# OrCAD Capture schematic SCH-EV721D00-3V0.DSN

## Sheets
1 Block Diagram
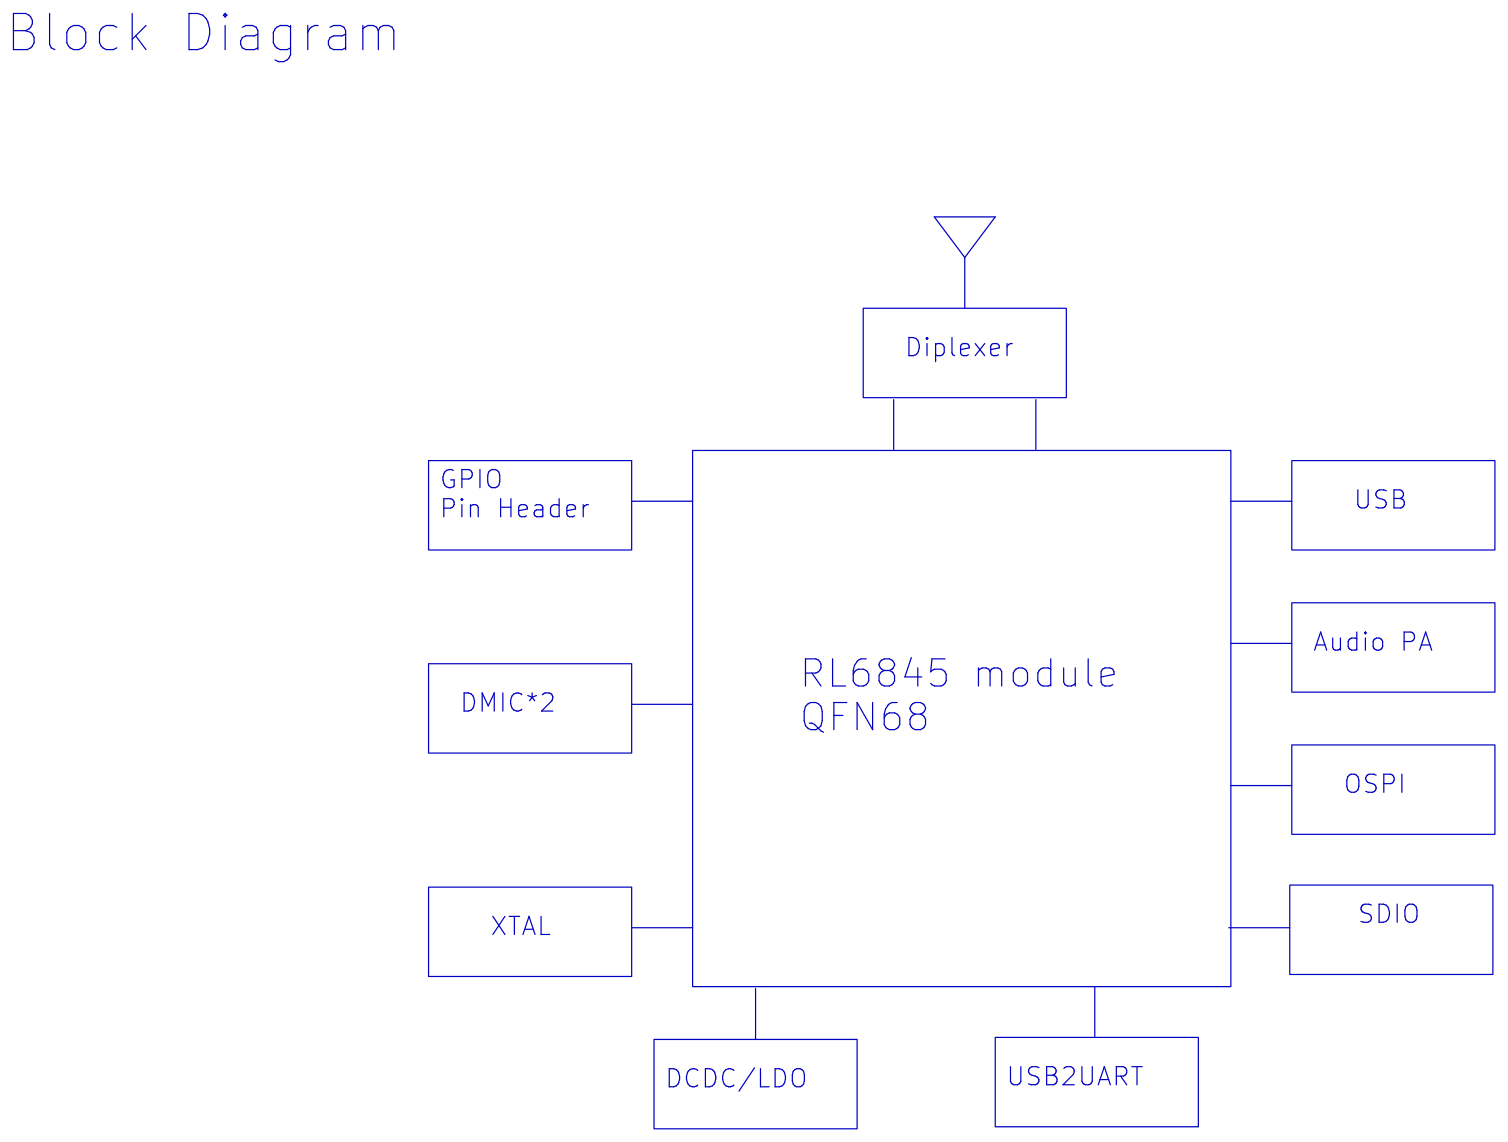
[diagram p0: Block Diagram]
2 Power Tree
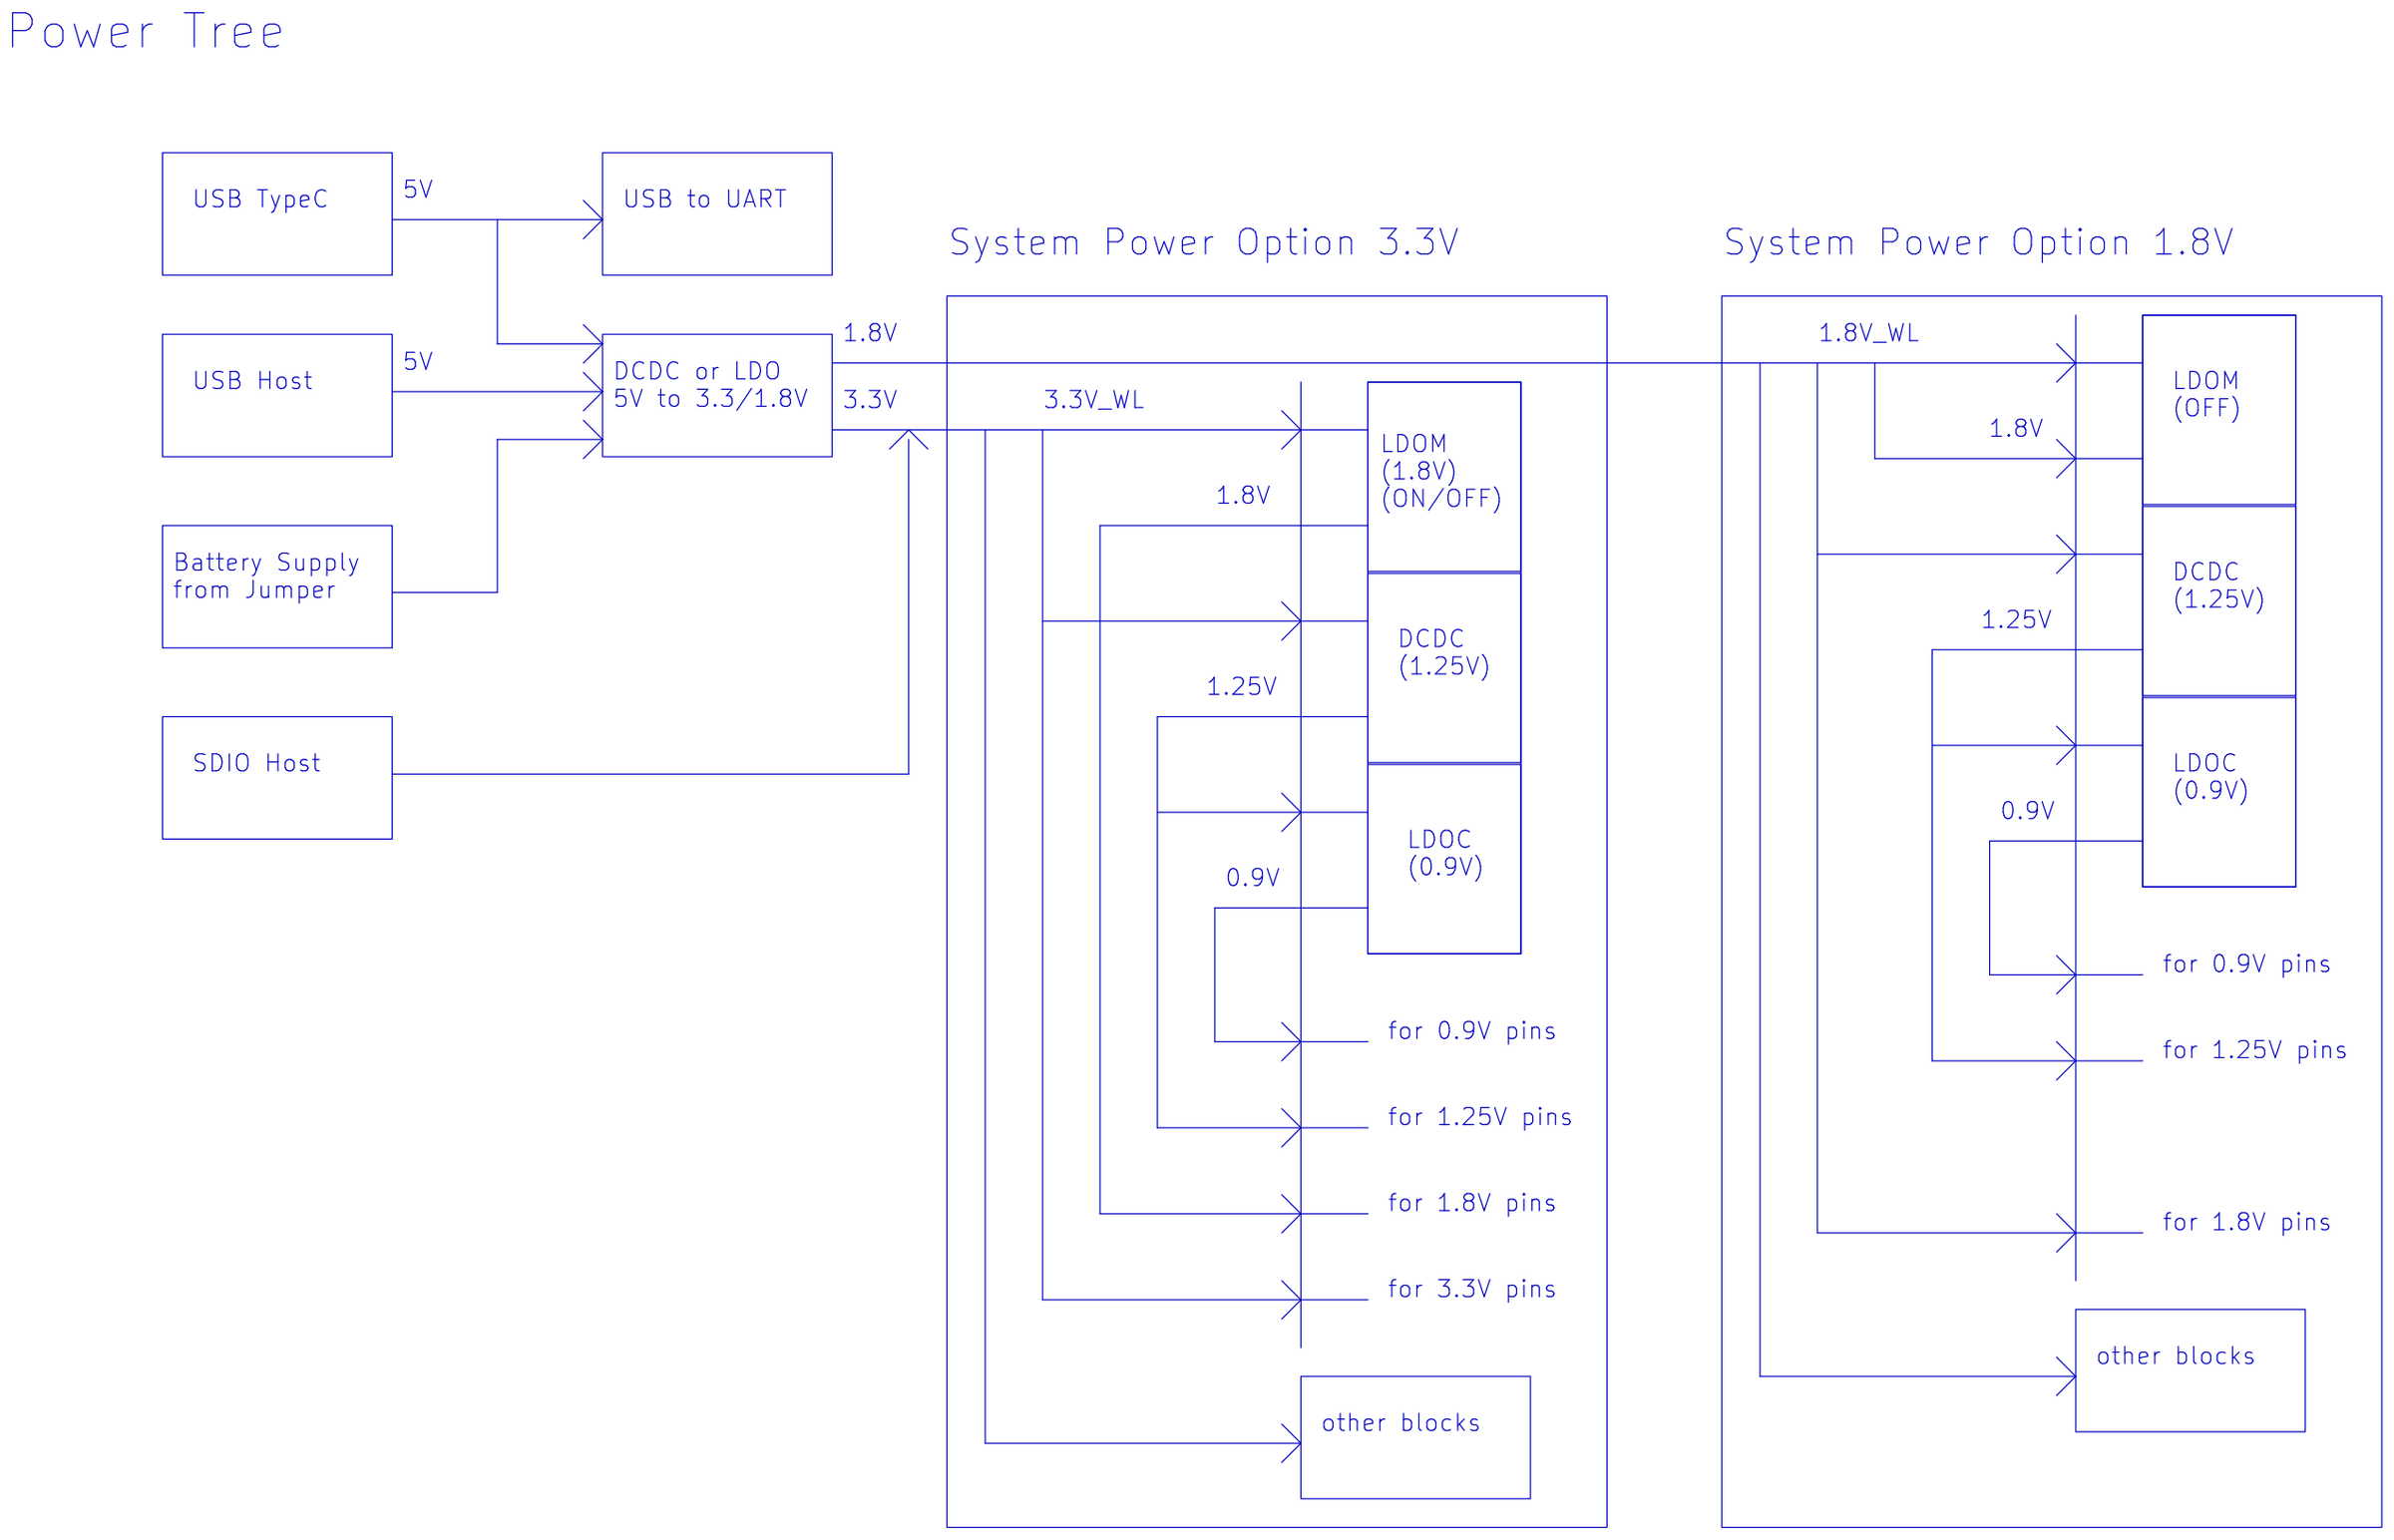
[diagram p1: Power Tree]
3 Power & USB: size A3; title: Power & USB
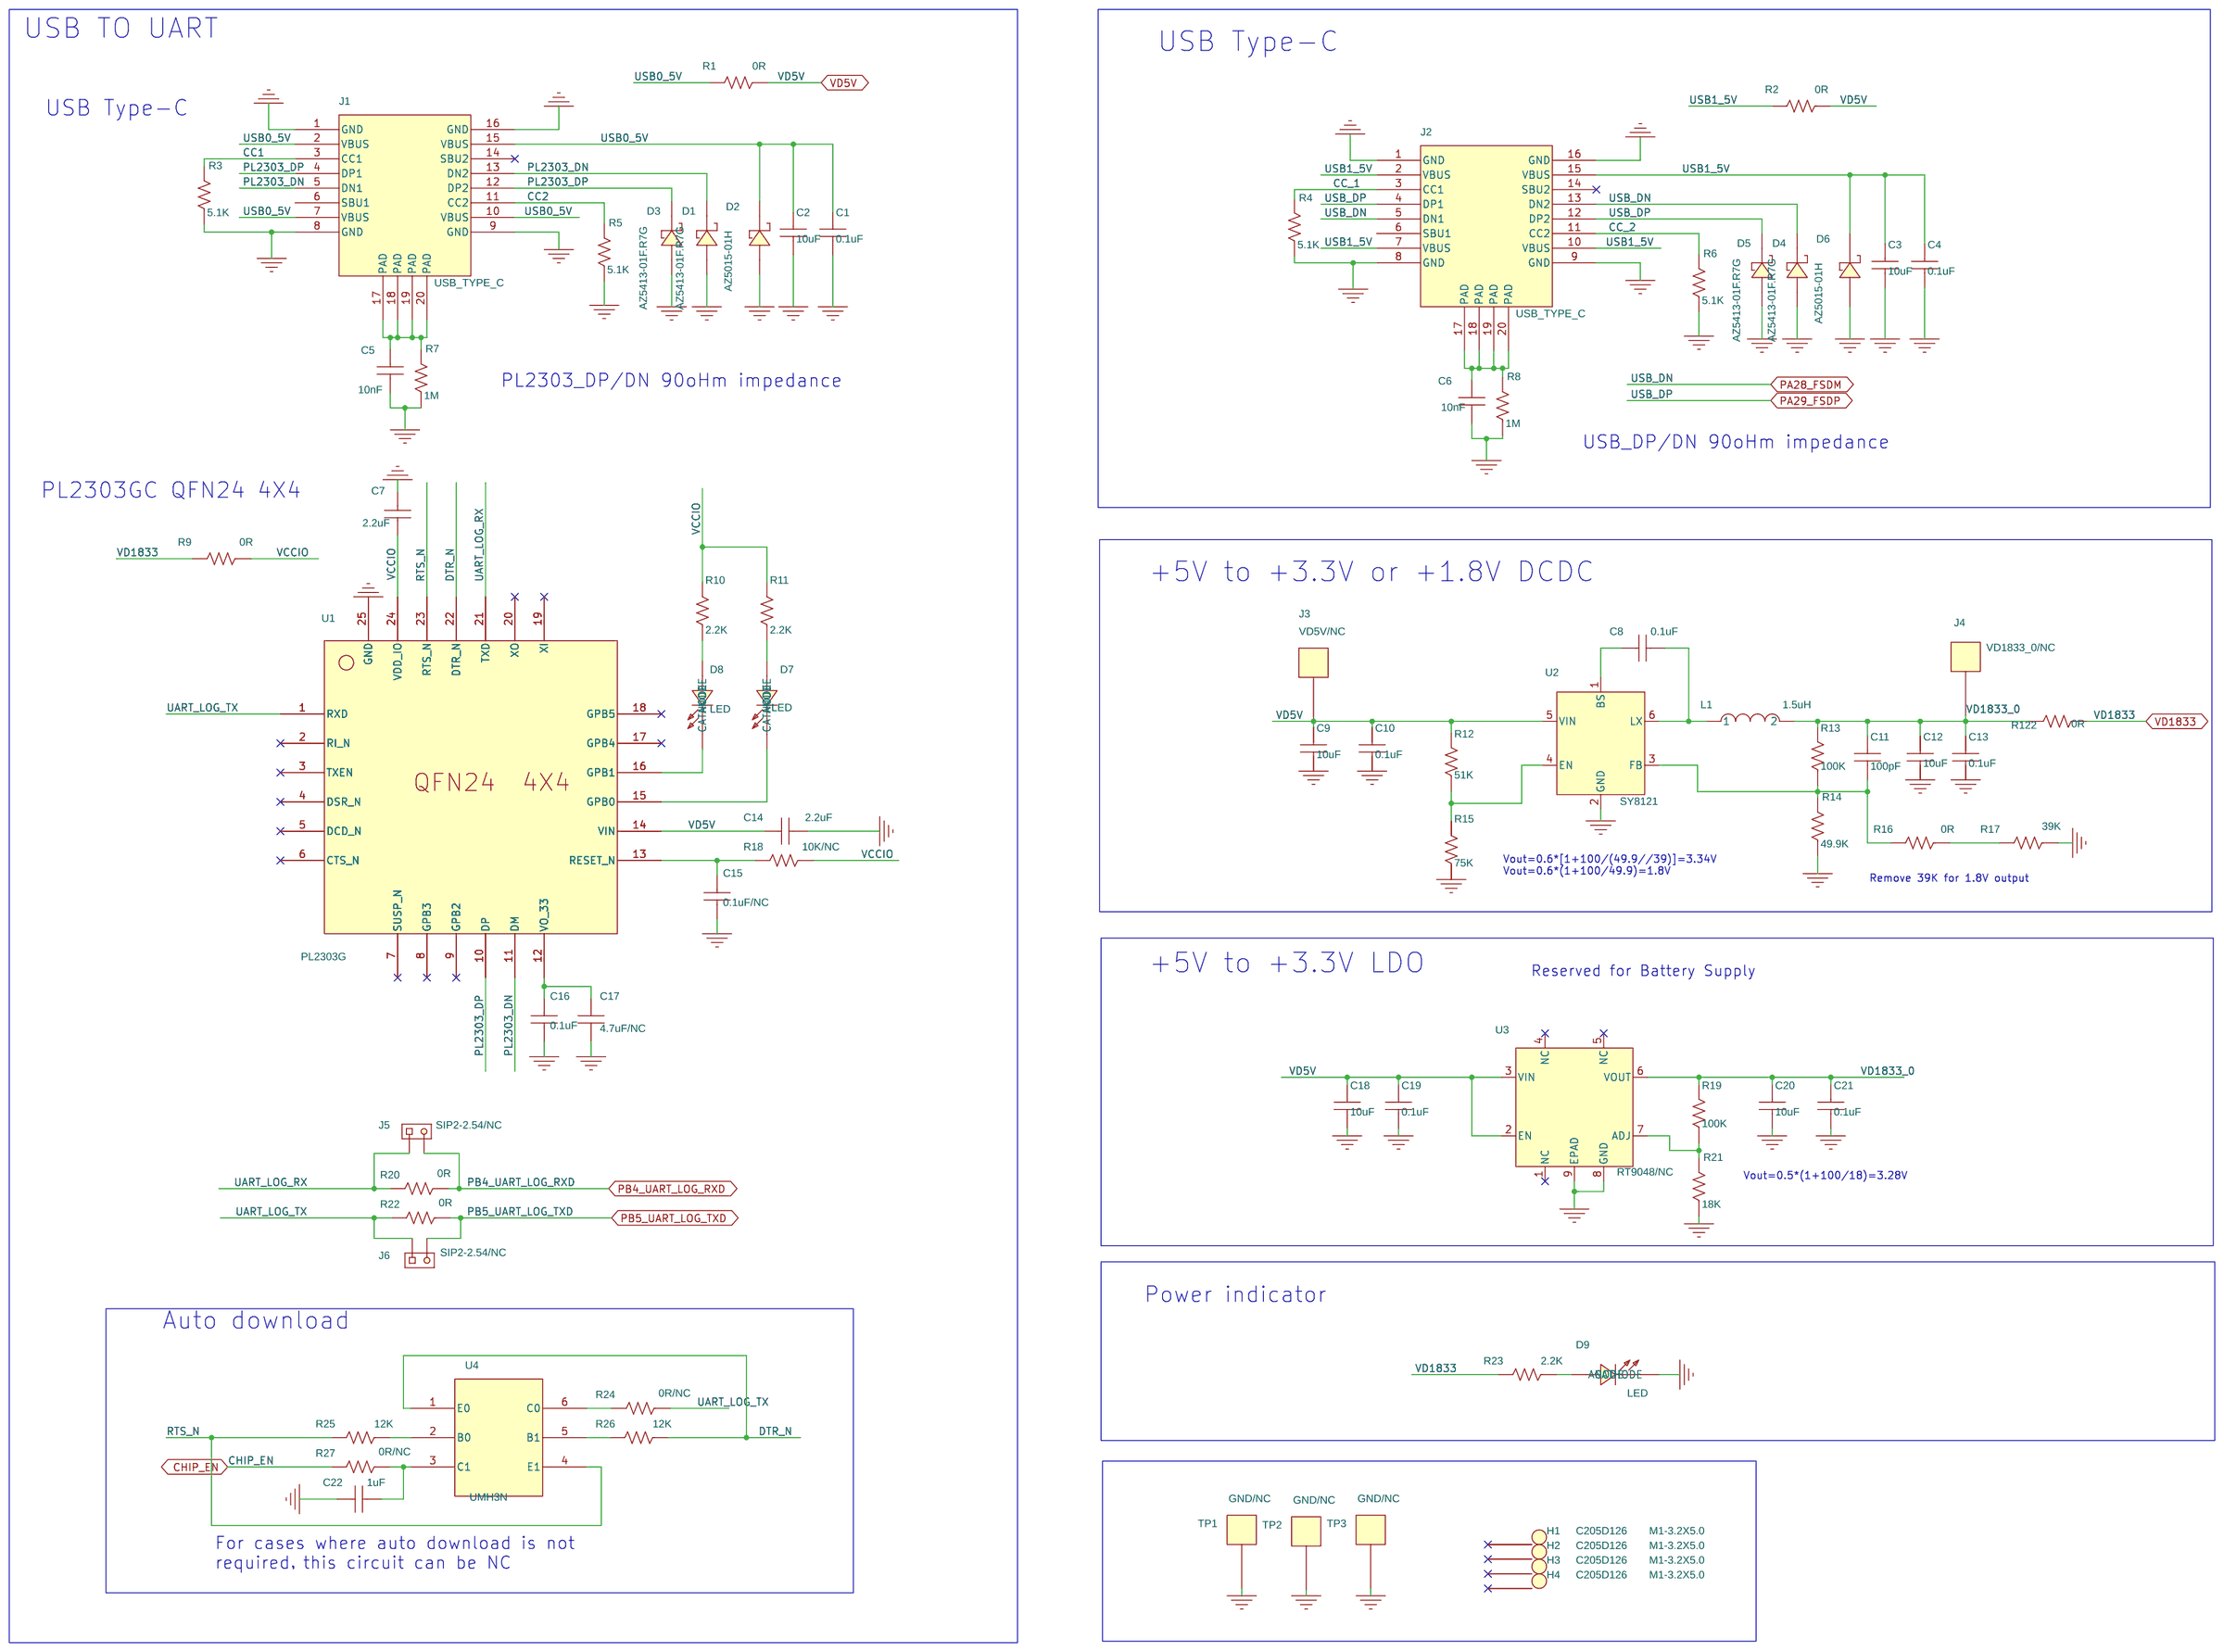
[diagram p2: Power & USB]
4 Module: size A3; title: Module
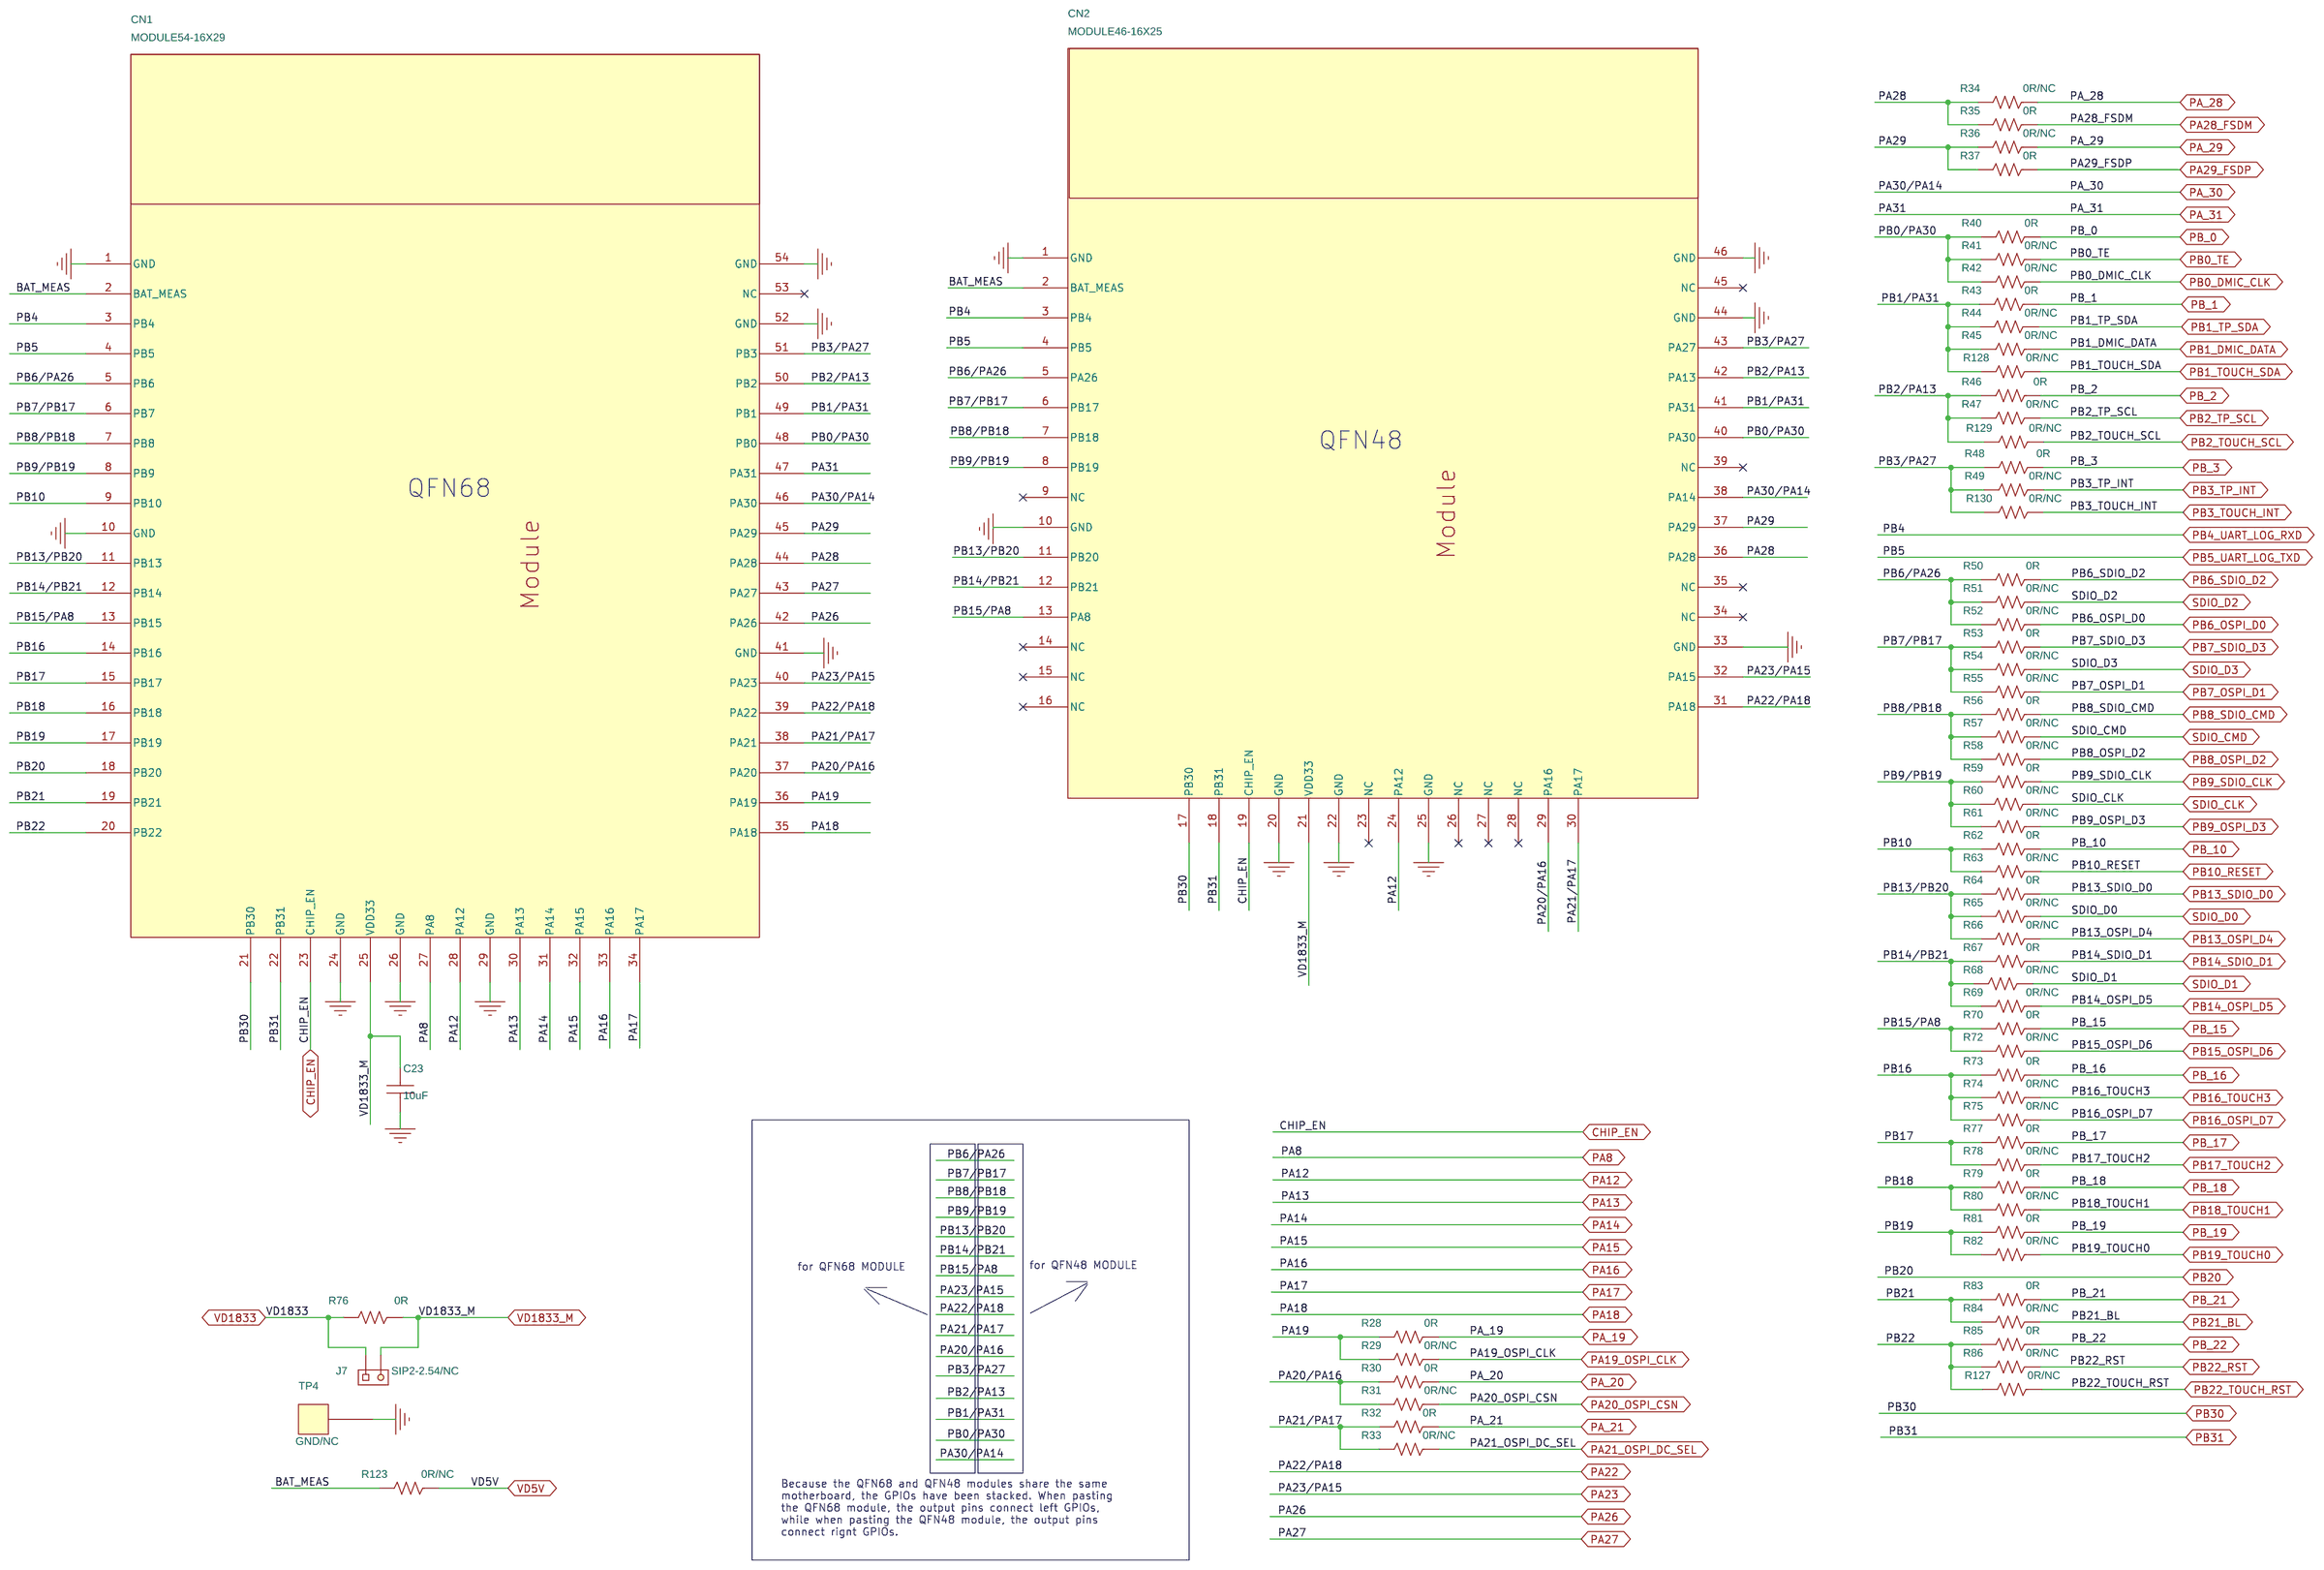
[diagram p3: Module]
5 Function: size B; title: Function
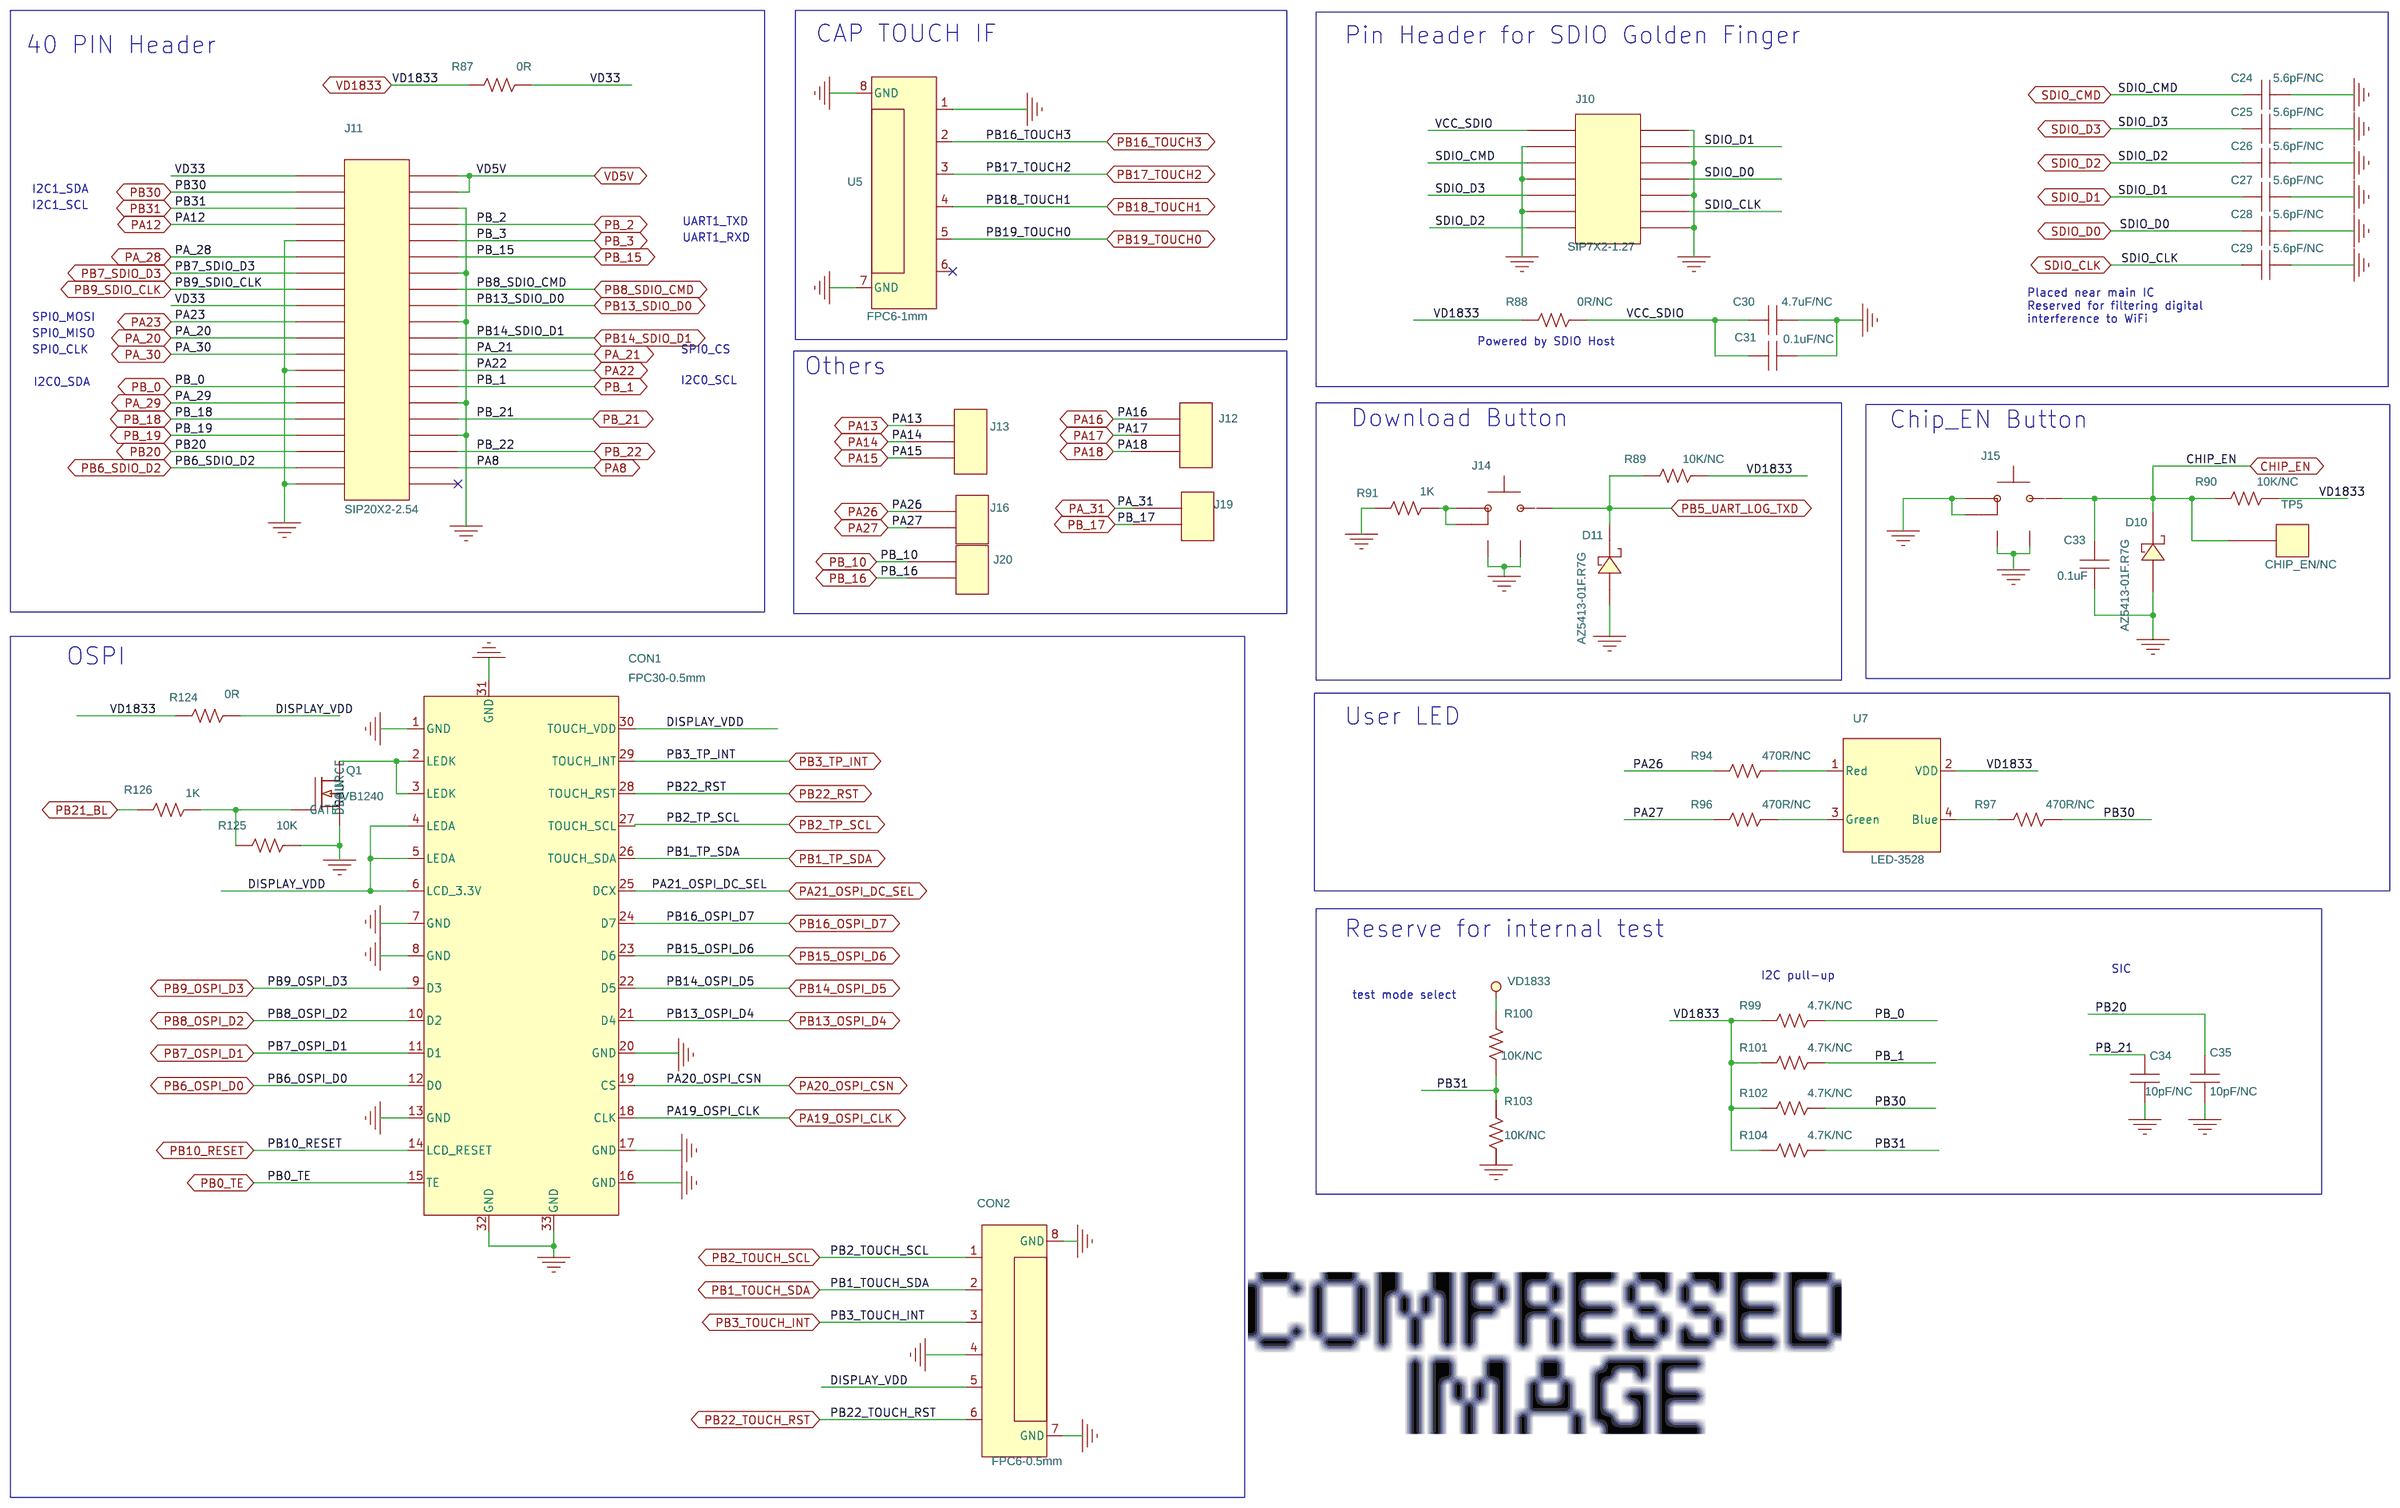
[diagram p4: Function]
6 Audio: size B; title: Audio
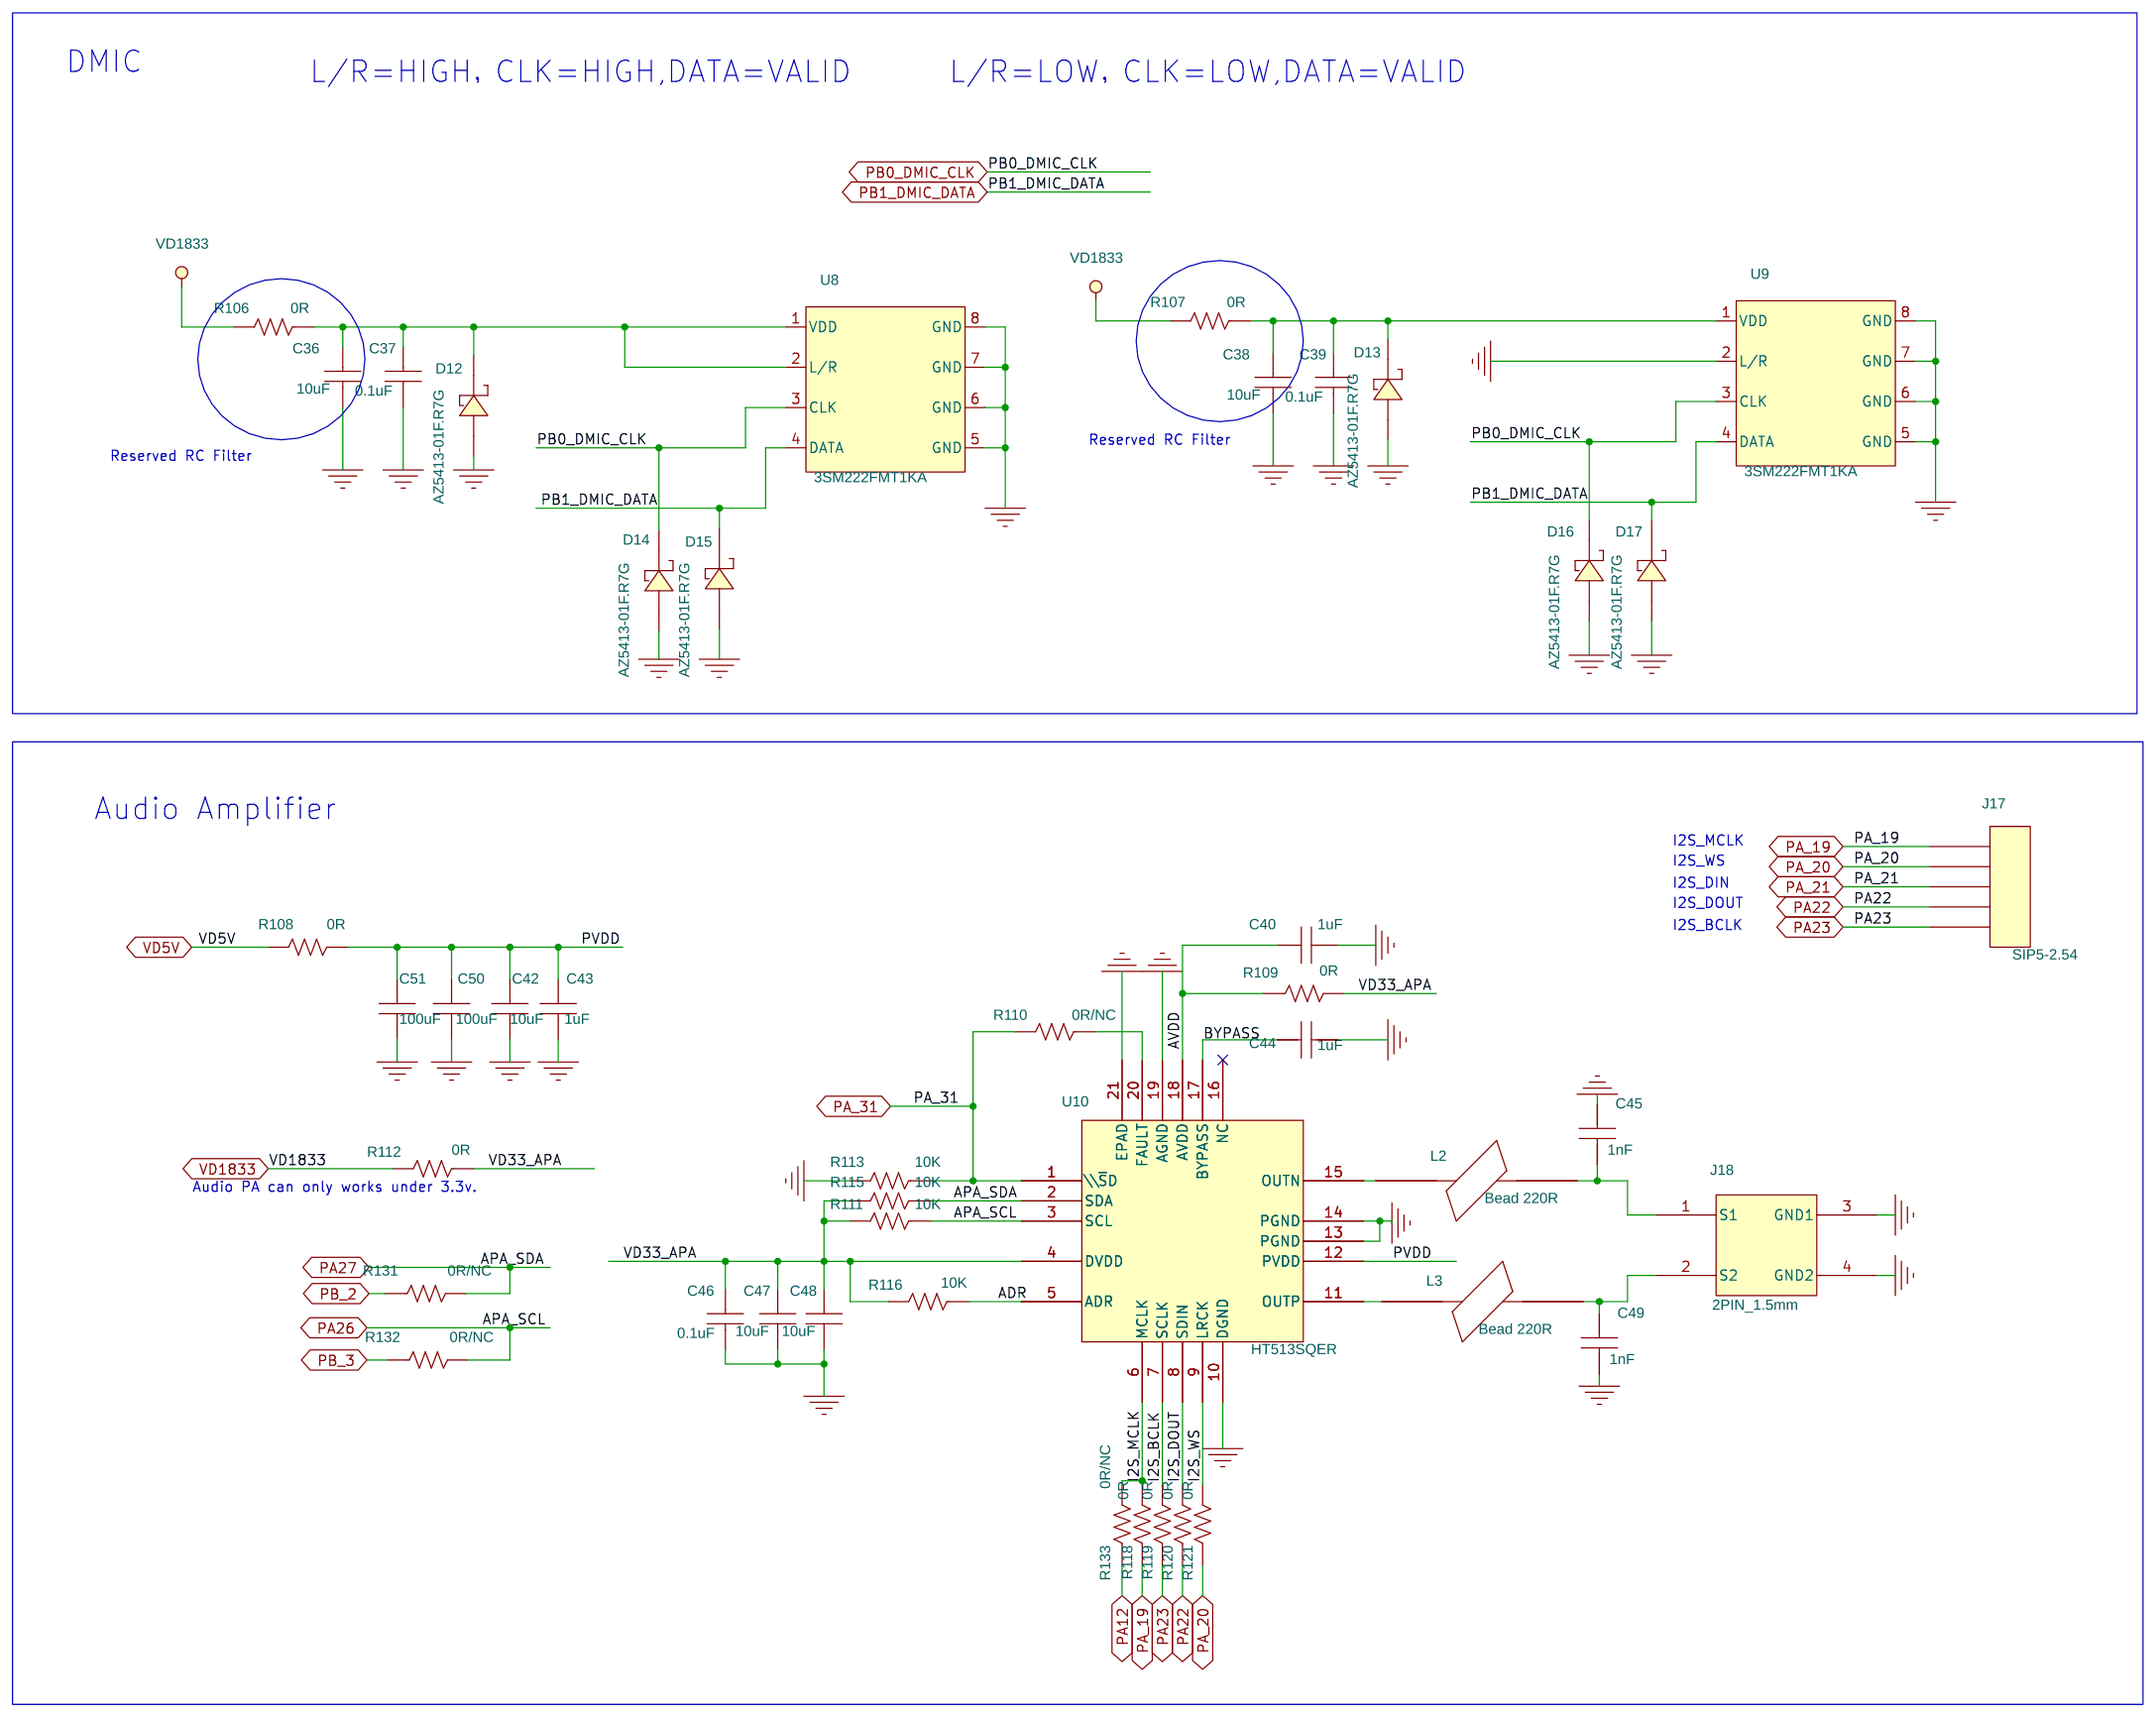
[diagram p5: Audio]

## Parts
sheet Audio
C36  10uF  [C0603]
C37  0.1uF  [C0402]
C38  10uF  [C0603]
C39  0.1uF  [C0402]
C40  1uF  [C0402]
C42  10uF  [C0603]
C43  1uF  [C0402]
C44  1uF  [C0402]
C45  1nF  [C0402]
C46  0.1uF  [C0402]
C47  10uF  [C0402]
C48  10uF  [C0402]
C49  1nF  [C0402]
C50  100uF  [C0805]
C51  100uF  [C0805]
D12  AZ5413-01F.R7G  [D0402-AZ5413]
D13  AZ5413-01F.R7G  [D0402-AZ5413]
D14  AZ5413-01F.R7G  [D0402-AZ5413]
D15  AZ5413-01F.R7G  [D0402-AZ5413]
D16  AZ5413-01F.R7G  [D0402-AZ5413]
D17  AZ5413-01F.R7G  [D0402-AZ5413]
J17  SIP5-2.54  [SIP5-2.54]
J18  2PIN_1.5mm  [Bar-Connector4]
L2  Bead 220R  [L0402]
L3  Bead 220R  [L0402]
R106  0R  [R0402]
R107  0R  [R0402]
R108  0R  [R0805]
R109  0R  [R0402]
R110  0R/NC  [R0402]
R111  10K  [R0402]
R112  0R  [R0402]
R113  10K  [R0402]
R115  10K  [R0402]
R116  10K  [R0402]
R118  0R  [R0402]
R119  0R  [R0402]
R120  0R  [R0402]
R121  0R  [R0402]
R131  0R/NC  [R0402]
R132  0R/NC  [R0402]
R133  0R/NC  [R0402]
U8  3SM222FMT1KA  [LGA8-4X3]
U9  3SM222FMT1KA  [LGA8-4X3]
U10  HT513SQER  [QFN16-0.5-4X4-EPAD2.65X2.65]
sheet Function
C24  5.6pF/NC  [C0402]
C25  5.6pF/NC  [C0402]
C26  5.6pF/NC  [C0402]
C27  5.6pF/NC  [C0402]
C28  5.6pF/NC  [C0402]
C29  5.6pF/NC  [C0402]
C30  4.7uF/NC  [C0603]
C31  0.1uF/NC  [C0402]
C33  0.1uF  [C0402]
C34  10pF/NC  [C0402]
C35  10pF/NC  [C0402]
CON1  FPC30-0.5mm  [FPC30-0.5-S]
CON2  FPC6-0.5mm  [FPC6-0.5]
D10  AZ5413-01F.R7G  [D0402-AZ5413]
D11  AZ5413-01F.R7G  [D0402-AZ5413]
J10  SIP7X2-1.27  [SIP7X2-1.27]
J11  SIP20X2-2.54  [SIP20X2-2.54]
J12  SIP3-2.54  [SIP3-2.54]
J13  SIP3-2.54  [SIP3-2.54]
J14  Reset Button  [SW-PB-5-KAN4548-1]
J15  Reset Button  [SW-PB-5-KAN4548-1]
J16  SIP2-2.54  [SIP2-2.54]
J19  SIP2-2.54  [SIP2-2.54]
J20  SIP2-2.54  [SIP2-2.54]
Q1  VB1240  [SOT-23]
R87  0R  [R0805]
R88  0R/NC  [R0805]
R89  10K/NC  [R0402]
R90  10K/NC  [R0402]
R91  1K  [R0402]
R94  470R/NC  [R0402]
R96  470R/NC  [R0402]
R97  470R/NC  [R0402]
R99  4.7K/NC  [R0402]
R100  10K/NC  [R0402]
R101  4.7K/NC  [R0402]
R102  4.7K/NC  [R0402]
R103  10K/NC  [R0402]
R104  4.7K/NC  [R0402]
R124  0R  [R0603]
R125  10K  [R0402]
R126  1K  [R0402]
TP5  CHIP_EN/NC  [SIP1-2.54]
U5  FPC6-1mm  [FPC6-1]
U7  LED-3528  [LED-3528]
sheet Module
C23  10uF  [C0603]
CN1  MODULE54-16X29  [MODULE54-16X29]
CN2  MODULE46-16X25  [MODULE46-16X25-EVB]
J7  SIP2-2.54/NC  [SIP2-2.54]
R28  0R  [R0402]
R29  0R/NC  [R0402]
R30  0R  [R0402]
R31  0R/NC  [R0402]
R32  0R  [R0402]
R33  0R/NC  [R0402]
R34  0R/NC  [R0402]
R35  0R  [R0402]
R36  0R/NC  [R0402]
R37  0R  [R0402]
R40  0R  [R0402]
R41  0R/NC  [R0402]
R42  0R/NC  [R0402]
R43  0R  [R0402]
R44  0R/NC  [R0402]
R45  0R/NC  [R0402]
R46  0R  [R0402]
R47  0R/NC  [R0402]
R48  0R  [R0402]
R49  0R/NC  [R0402]
R50  0R  [R0402]
R51  0R/NC  [R0402]
R52  0R/NC  [R0402]
R53  0R  [R0402]
R54  0R/NC  [R0402]
R55  0R/NC  [R0402]
R56  0R  [R0402]
R57  0R/NC  [R0402]
R58  0R/NC  [R0402]
R59  0R  [R0402]
R60  0R/NC  [R0402]
R61  0R/NC  [R0402]
R62  0R  [R0402]
R63  0R/NC  [R0402]
R64  0R  [R0402]
R65  0R/NC  [R0402]
R66  0R/NC  [R0402]
R67  0R  [R0402]
R68  0R/NC  [R0402]
R69  0R/NC  [R0402]
R70  0R  [R0402]
R72  0R/NC  [R0402]
R73  0R  [R0402]
R74  0R/NC  [R0402]
R75  0R/NC  [R0402]
R76  0R  [R0805]
R77  0R  [R0402]
R78  0R/NC  [R0402]
R79  0R  [R0402]
R80  0R/NC  [R0402]
R81  0R  [R0402]
R82  0R/NC  [R0402]
R83  0R  [R0402]
R84  0R/NC  [R0402]
R85  0R  [R0402]
R86  0R/NC  [R0402]
R123  0R/NC  [R0402]
R127  0R/NC  [R0402]
R128  0R/NC  [R0402]
R129  0R/NC  [R0402]
R130  0R/NC  [R0402]
TP4  GND/NC  [SIP1-2.54]
sheet Power & USB
C1  0.1uF  [C0402]
C2  10uF  [C0603]
C3  10uF  [C0603]
C4  0.1uF  [C0402]
C5  10nF  [C0402]
C6  10nF  [C0402]
C7  2.2uF  [C0402]
C8  0.1uF  [C0402]
C9  10uF  [C0603]
C10  0.1uF  [C0402]
C11  100pF  [C0402]
C12  10uF  [C0603]
C13  0.1uF  [C0402]
C14  2.2uF  [C0402]
C15  0.1uF/NC  [C0402]
C16  0.1uF  [C0402]
C17  4.7uF/NC  [C0402]
C18  10uF  [C0603]
C19  0.1uF  [C0402]
C20  10uF  [C0603]
C21  0.1uF  [C0402]
C22  1uF  [C0402]
D1  AZ5413-01F.R7G  [D0402-AZ5413]
D2  AZ5015-01H  [SOD-523]
D3  AZ5413-01F.R7G  [D0402-AZ5413]
D4  AZ5413-01F.R7G  [D0402-AZ5413]
D5  AZ5413-01F.R7G  [D0402-AZ5413]
D6  AZ5015-01H  [SOD-523]
D7  LED  [LED-0603]
D8  LED  [LED-0603]
D9  LED  [LED-0603]
H1  C205D126  [M1-3.2X5.0]
H2  C205D126  [M1-3.2X5.0]
H3  C205D126  [M1-3.2X5.0]
H4  C205D126  [M1-3.2X5.0]
J1  USB_TYPE_C  [USB-TYPEC-12P-SMD]
J2  USB_TYPE_C  [USB-TYPEC-12P-SMD]
J3  VD5V/NC  [SIP1-2.54]
J4  VD1833_0/NC  [SIP1-2.54]
J5  SIP2-2.54/NC  [SIP2-2.54]
J6  SIP2-2.54/NC  [SIP2-2.54]
L1  1.5uH  [L4442]
R1  0R  [R0805]
R2  0R  [R0805]
R3  5.1K  [R0402]
R4  5.1K  [R0402]
R5  5.1K  [R0402]
R6  5.1K  [R0402]
R7  1M  [R0402]
R8  1M  [R0402]
R9  0R  [R0402]
R10  2.2K  [R0402]
R11  2.2K  [R0402]
R12  51K  [R0402]
R13  100K  [R0402]
R14  49.9K  [R0402]
R15  75K  [R0402]
R16  0R  [R0402]
R17  39K  [R0402]
R18  10K/NC  [R0402]
R19  100K  [R0402]
R20  0R  [R0402]
R21  18K  [R0402]
R22  0R  [R0402]
R23  2.2K  [R0402]
R24  0R/NC  [R0402]
R25  12K  [R0402]
R26  12K  [R0402]
R27  0R/NC  [R0402]
R122  0R  [R0805]
TP1  GND/NC  [SIP1-2.54]
TP2  GND/NC  [SIP1-2.54]
TP3  GND/NC  [SIP1-2.54]
U1  PL2303G  [UQFN24-0.5-4X4-EP1.5X1.5]
U2  SY8121  [SOT-23-6]
U3  RT9048/NC  [SOP8-1.27-5.31-EP2.15]
U4  UMH3N  [SOT-363-1.6]

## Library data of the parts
C2 C3 C9 C12 C20 C23 C36 C38 C42 = CAPACITOR_NON-POL_0: Part Number: 0603X106K250CT; Part Type: Ceramic; Tolerance,Voltage,Dielectric,Lead Free(Y/N): ±10%,25V,X5R; Datasheet: \\172.29.17.1\cn\WLAN\WLAN2\boarddesignLIB\55_component_database\Datasheet\Capacitor\Capacitor_Walsin_MLCC.pdf
C1 C4 C8 C10 C13 C15 C16 C19 C21 C37 C39 = CAPACITOR_NON-POL_0: Part Number: 0402B104K250CT; Part Type: Ceramic; Tolerance,Voltage,Dielectric,Lead Free(Y/N): ±10%,25V X7R,; Datasheet: \\172.29.17.1\cn\WLAN\WLAN2\boarddesignLIB\06_component_database\Datasheet\Capacitor\Capacitor_Walsin_MLCC.pdf
C22 C40 C43 C44 = CAPACITOR_NON-POL_0: Part Number: 0402X105K250CT; Voltage: 25V; Datasheet: \\172.29.17.1\cn\WLAN\WLAN2\boarddesignLIB\84_component_database\Datasheet\Capacitor\Capacitor_Walsin_MLCC.pdf
C45 C49 = CAPACITOR_NON-POL_0: 10%,50V,X7R; Manufacturer: WALSIN; Part Number: 0402B102K500CT; Voltage: 50V; Datasheet: \\172.29.17.1\cn\WLAN\WLAN2\boarddesignLIB\74_component_database\Datasheet\Capacitor\Capacitor_Walsin_MLCC.pdf
C46 = CAPACITOR_NON-POL_0: ±10%,25V X7R,; Manufacturer: WALSIN; Part Number: 0402B104K250CT; Voltage: 25V; Datasheet: \\172.29.17.1\cn\WLAN\WLAN2\boarddesignLIB\06_component_database\Datasheet\Capacitor\Capacitor_Walsin_MLCC.pdf
C47 C48 = CAPACITOR_NON-POL_0: ±10%,16V,X5R; Manufacturer: WALSIN; Part Number: 0402X106K160CT; Voltage: 16V; Datasheet: \\172.29.17.1\cn\WLAN\WLAN2\boarddesignLIB\54_component_database\Datasheet\Capacitor\Capacitor_Walsin_MLCC.pdf
C50 C51 = CAPACITOR_NON-POL_0: ±10%,6.3V,X5R; Manufacturer: WALSIN; Part Number: 1206X226K6R3CT; Voltage: 6.3V; Datasheet: \\172.29.17.1\cn\WLAN\WLAN2\boarddesignLIB\118_component_database\Datasheet\Capacitor\Capacitor_Walsin_MLCC.pdf
D1 D3-D5 D10-D17 = Uni-directional_ESD_0: Uni-directional, 3.6V; Part Number: AZ5413-01F; Datasheet: \\172.29.17.1\cn\WLAN\WLAN2\boarddesignLIB\01_component_database\Datasheet\TVS\TVS_Amazing_AZ5413-01F.pdf
J17 = CON5: Pin Header
J18 = TJ-2702: Bar Connector; Part Number: TJ-2702SN719-R
L2 L3 = Bead: Part Number: BKP1005EM221-T; Datasheet: \\172.29.17.1\cn\WLAN\WLAN2\boarddesignLIB\01_component_database\Datasheet\Bead-EMI Optimization\Bead_Taiyo yuden_FBMH3225HM601NT.pdf
R20 R22 R24 R27 R106 R107 R109 R110 R112 R118-R121 R131-R133 = RES_0: Part Number: WR04X000PTL; Tolerance,Voltage,Dielectric,Lead Free(Y/N): JUMPER; Datasheet: \\172.29.17.1\cn\WLAN\WLAN2\boarddesignLIB\64_component_database\Datasheet\Resistor\Resistor_Walsin_chipR.pdf
R1 R2 R76 R87 R88 R108 R122 = RES_0: Part Number: WR08X000PTL; Part type: Chip Resistor; Tolerance,Voltage,Dielectric,Lead Free(Y/N): JUMPER; Datasheet: \\172.29.17.1\cn\WLAN\WLAN2\boarddesignLIB\65_component_database\Datasheet\ResistorResistor_Walsin_chipR.pdf
R111 R116 = RES_0: Part Number: WR04X1002 FTL; Part type: Chip Resistor; Tolerance,Voltage,Dielectric,Lead Free(Y/N): +/-1%; Datasheet: \\172.29.17.1\cn\WLAN\WLAN2\boarddesignLIB\190_component_database\Datasheet\ResistorResistor_Walsin, chipR.pdf
R113 R115 = RES_0: Part Number: WR04X1002 FTL; Tolerance,Voltage,Dielectric,Lead Free(Y/N): JUMPER; Datasheet: \\172.29.17.1\cn\WLAN\WLAN2\boarddesignLIB\64_component_database\Datasheet\Resistor\Resistor_Walsin_chipR.pdf
U8 U9 = DMIC_0: Sensitivity deviation within ±1dB; Datasheet: \\172.29.17.1\cn\WLAN\WLAN2\boarddesignLIB\01_component_database\Datasheet\Audio Component\DMIC_Solid state system_3SM222FMT1KA Datasheet V1.1(1).pdf
U10 = APA_4: 2.8W，; Datasheet: \\172.29.17.1\cn\WLAN\WLAN2\boarddesignLIB\01_component_database\Datasheet\Audio Component\Audio PA_Heroic_HT513SQER.pdf
C24-C29 = CAPACITOR_NON-POL_0: Part Number: RF15N5R6B500CT; Voltage: 50V; Datasheet: \\172.29.17.1\cn\WLAN\WLAN2\boarddesignLIB\165_component_database\Datasheet\Capacitor\Capacitor_Walsin_MLCC.pdf
C30 = CAPACITOR_NON-POL_0: Part Number: 0603X475K250CT; Voltage: 25V; Datasheet: \\172.29.17.1\cn\WLAN\WLAN2\boarddesignLIB\149_component_database\Datasheet\Capacitor\Capacitor_Walsin_MLCC.pdf
C31 C33 = CAPACITOR_NON-POL_0: Part Number: 0402B104K250CT; Voltage: 25V; Datasheet: \\172.29.17.1\cn\WLAN\WLAN2\boarddesignLIB\06_component_database\Datasheet\Capacitor\Capacitor_Walsin_MLCC.pdf
C34 C35 = CAPACITOR_NON-POL_0: Part Number: 0402N100J500CT; Voltage: 50V; Datasheet: \\172.29.17.1\cn\WLAN\WLAN2\boarddesignLIB\52_component_database\Datasheet\Capacitor\Capacitor_Walsin_MLCC.pdf
CON1 = FPC-30-S_2: 下接翻盖，兼容FPC20，; Part Number: FPC30
CON2 = FPC-6: Manufacturer: HRS; Part Number: FH19C-6S-0.5SH; Datasheet: \\172.29.17.1\cn\WLAN\WLAN2\boarddesignLIB\01_component_database\Datasheet\Connector\FPC_HRS_FH19C-6S-0.5SH_2019-09-03.pdf
J10 = CON14A: Pin Header
J11 = CON40A: Pin Header; Part Type: Pin Header
J12 J13 = CON3: Pin Header
J14 J15 = BUTTON_(RST)_0
J16 J19 J20 = CON2: Pin Header
Q1 = MOSFET_N: N沟道20V 6A; Manufacturer: Vbsemi; Datasheet: \\172.29.17.1\cn\WLAN\WLAN2\boarddesignLIB\01_component_database\Datasheet\Triode-MOS Tube-Transistor\N-MOS_VBsemi_VB1240.pdf
R89 R90 R100 R103 = RES_0: Part Number: WR04X1002 FTL; Tolerance,Voltage,Dielectric,Lead Free(Y/N): +/-1%; Datasheet: \\172.29.17.1\cn\WLAN\WLAN2\boarddesignLIB\191_component_database\Datasheet\Resistor\Resistor_Walsin_chipR.pdf
R91 = RES_0: Part Number: WR04X1001FTL; Tolerance,Voltage,Dielectric,Lead Free(Y/N): +/-1%; Datasheet: \\172.29.17.1\cn\WLAN\WLAN2\boarddesignLIB\154_component_database\Datasheet\Resistor\Resistor_Walsin_chipR.pdf
R94 R96 R97 = RES_0: Part Number: WR04X471 JTL; Tolerance,Voltage,Dielectric,Lead Free(Y/N): +/-5%; Datasheet: \\172.29.17.1\cn\WLAN\WLAN2\boarddesignLIB\141_component_database\Datasheet\Resistor\Resistor_Walsin_chipR.pdf
R99 R101 R102 R104 = RES_0: Part Number: WR04X4701FTL; Tolerance,Voltage,Dielectric,Lead Free(Y/N): +/-1%; Datasheet: \\172.29.17.1\cn\WLAN\WLAN2\boarddesignLIB\179_component_database\Datasheet\Resistor\Resistor_Walsin_chipR.pdf
R124 = RES_0: JUMPER; Manufacturer: WALSIN; Part Number: WR06X000PTL; Datasheet: \\172.29.17.1\cn\WLAN\WLAN2\boarddesignLIB\65_component_database\Datasheet\Resistor\Resistor_Walsin_chipR.pdf
R125 = RES_0: +/-1%; Manufacturer: WALSIN; Part Number: WR04X1002 FTL; Datasheet: \\172.29.17.1\cn\WLAN\WLAN2\boarddesignLIB\191_component_database\Datasheet\Resistor\Resistor_Walsin_chipR.pdf
R126 = RES_0: +/-1%; Manufacturer: WALSIN; Part Number: WR04X1001FTL; Datasheet: \\172.29.17.1\cn\WLAN\WLAN2\boarddesignLIB\154_component_database\Datasheet\Resistor\Resistor_Walsin_chipR.pdf
TP1-TP3 TP5 = CON1: Pin Header
U5 = FPC-6: 1．0mm-6P.下接翻盖; Part Number: FPC6
U7 = LED_1: SMT LED; Part Number: S3528EHMRGBTP-H5-D; Part Type: LED; Datasheet: \\172.29.17.1\cn\WLAN\WLAN2\boarddesignLIB\01_component_database\Datasheet\Optocoupler-LED-Photoelectric DeviceLED_Inbright, S3528EHMRGBTP-H5-D 3528RGB.pdf
CN1 = R0402_4.06K_WALSIN
CN2 = R0402_11.06K_WALSIN
J5-J7 = HEADER2_0: Pin Header; Part Type: Pin Header
R9 R16 R28-R37 R40-R70 R72-R75 R77-R86 R123 R127-R130 = RES_0: Part Number: WR04X000PTL; Part type: Chip Resistor; Tolerance,Voltage,Dielectric,Lead Free(Y/N): JUMPER; Datasheet: \\172.29.17.1\cn\WLAN\WLAN2\boarddesignLIB\63_component_database\Datasheet\ResistorResistor_Walsin_chipR.pdf
J3 J4 TP4 = CON1: Pin Header; Part Type: Pin Header
C5 C6 = CAPACITOR_NON-POL_0: Part Number: 0402B103K250CT; Part Type: Ceramic; Tolerance,Voltage,Dielectric,Lead Free(Y/N): ±10%,25V,X7R; Datasheet: \\172.29.17.1\cn\WLAN\WLAN2\boarddesignLIB\50_component_database\Datasheet\Capacitor\Capacitor_Walsin_MLCC.pdf
C7 C14 = CAPACITOR_NON-POL_0: Part Number: 0402X225K250CT; Part Type: Ceramic; Tolerance,Voltage,Dielectric,Lead Free(Y/N): ±10%,25V,X5R; Datasheet: \\172.29.17.1\cn\WLAN\WLAN2\boarddesignLIB\93_component_database\Datasheet\Capacitor\Capacitor_Walsin_MLCC.pdf
C11 = CAPACITOR_NON-POL_0: Part Number: 0402N101J500CT; Part Type: Ceramic; Tolerance,Voltage,Dielectric,Lead Free(Y/N): ±5%,50V,NPO; Datasheet: \\172.29.17.1\cn\WLAN\WLAN2\boarddesignLIB\47_component_database\Datasheet\Capacitor\Capacitor_Walsin_MLCC.pdf
C17 = CAPACITOR_NON-POL_0: Part Number: 0402X475M160CT; Part Type: Ceramic; Tolerance,Voltage,Dielectric,Lead Free(Y/N): ±20%,16V,X5R; Datasheet: \\172.29.17.1\cn\WLAN\WLAN2\boarddesignLIB\147_component_database\Datasheet\Capacitor\Capacitor_Walsin_MLCC.pdf
C18 = CAPACITOR_NON-POL_0: Part Number: 0402X106K250CT; Part Type: Ceramic; Tolerance,Voltage,Dielectric,Lead Free(Y/N): ±10%,25V,X5R; Datasheet: \\172.29.17.1\cn\WLAN\WLAN2\boarddesignLIB\55_component_database\Datasheet\Capacitor\Capacitor_Walsin_MLCC.pdf
D2 D6 = Uni-directional_ESD_0: Uni-directional, 6V; Datasheet: \\172.29.17.1\cn\WLAN\WLAN2\boarddesignLIB\01_component_database\Datasheet\TVS\TVS_Amazing_AZ5015-01H.pdf
D7-D9 = LED_0: SMD  黄绿色 红色
H1-H4 = HOLE_PTH: FOR PEGATRON ENTEK; Colay_Alternate: N/A; Colay_Group: N/A; Component_Name: TOOLING HOLE C205D126; Data_Sheet: K:\DataSheet\13-MECHANICAL\T-SH00002166.zip; Device: hole_c205d126; Modify_data: 2013/01/17; Optional: N/A; Package_Type: DIP; Part Number: T-SH00002166; Part Type: 13MECHANICAL\HOLE; Subsystem_ID: N/A
J1 J2 = USB_TYPE_C_0: TYPE C 16 PIN TOP MOUNT SMT; Manufacturer: Molex; Part Number: 2171790001; Datasheet: \\172.29.17.1\cn\WLAN\WLAN2\boarddesignLIB\01_component_database\Datasheet\Connector\Type-C_Molex_2171790001_sd.pdf
L1 = INDUCTOR_POWER: Part Number: MWSA0402-1R5MT; Part Type: Power Inductor; Õ`²îÖµTolerance(nH/%),Q‚Ž(min): 3A,±20%
R3-R6 = RES_0: Part Number: WR04X5101FTL; Tolerance,Voltage,Dielectric,Lead Free(Y/N): +/-1%; Datasheet: \\172.29.17.1\cn\WLAN\WLAN2\boarddesignLIB\180_component_database\Datasheet\Resistor\Resistor_Walsin_chipR.pdf
R7 R8 = RES_0: Part Number: WR04X1004FTL; Tolerance,Voltage,Dielectric,Lead Free(Y/N): +/-1%; Datasheet: \\172.29.17.1\cn\WLAN\WLAN2\boarddesignLIB\252_component_database\Datasheet\Resistor\Resistor_Walsin_chipR.pdf
R10 R11 = RES_0: Part Number: WR04X222 JTL; Part type: Chip Resistor; Tolerance,Voltage,Dielectric,Lead Free(Y/N): +/-5%; Datasheet: \\172.29.17.1\cn\WLAN\WLAN2\boarddesignLIB\164_component_database\Datasheet\ResistorResistor_Walsin, chipR.pdf
R12 = RES_0: Part Number: WR04X5102FTL; Part type: Chip Resistor; Tolerance,Voltage,Dielectric,Lead Free(Y/N): +/-1%; Datasheet: \\172.29.17.1\cn\WLAN\WLAN2\boarddesignLIB\215_component_database\Datasheet\ResistorResistor_Walsin, chipR.pdf
R13 R19 = RES_0: Part Number: WR04X1003FTL; Part type: Chip Resistor; Tolerance,Voltage,Dielectric,Lead Free(Y/N): +/-1%; Datasheet: \\172.29.17.1\cn\WLAN\WLAN2\boarddesignLIB\223_component_database\Datasheet\ResistorResistor_Walsin, chipR.pdf
R14 = RES_0: Part Number: WR04X4992FTL; Tolerance,Voltage,Dielectric,Lead Free(Y/N): +/-1%; Datasheet: \\172.29.17.1\cn\WLAN\WLAN2\boarddesignLIB\215_component_database\Datasheet\Resistor\Resistor_Walsin_chipR.pdf
R15 = RES_0: Part Number: WR04X7502FTL; Part type: Chip Resistor; Tolerance,Voltage,Dielectric,Lead Free(Y/N): +/-1%; Datasheet: \\172.29.17.1\cn\WLAN\WLAN2\boarddesignLIB\220_component_database\Datasheet\ResistorResistor_Walsin, chipR.pdf
R17 = RES_0: Part Number: WR04X3902FTL; Tolerance,Voltage,Dielectric,Lead Free(Y/N): +/-1%; Datasheet: \\172.29.17.1\cn\WLAN\WLAN2\boarddesignLIB\211_component_database\Datasheet\Resistor\Resistor_Walsin_chipR.pdf
R18 = RES_0: Part Number: WR04X1002 FTL; Part type: Chip Resistor; Tolerance,Voltage,Dielectric,Lead Free(Y/N): +/-1%; Datasheet: \\172.29.17.1\cn\WLAN\WLAN2\boarddesignLIB\190_component_database\Datasheet\ResistorResistor_Walsin_chipR.pdf
R21 = RES_0: Part Number: WR04X1802 FTL; Tolerance,Voltage,Dielectric,Lead Free(Y/N): +/-1%; Datasheet: \\172.29.17.1\cn\WLAN\WLAN2\boarddesignLIB\200_component_database\Datasheet\Resistor\Resistor_Walsin_chipR.pdf
R23 = RES_0: Part Number: WR04X222 JTL; Tolerance,Voltage,Dielectric,Lead Free(Y/N): +/-5%; Datasheet: \\172.29.17.1\cn\WLAN\WLAN2\boarddesignLIB\165_component_database\Datasheet\Resistor\Resistor_Walsin_chipR.pdf
R25 R26 = RES_0: Part Number: WR04X123 JTL; Tolerance,Voltage,Dielectric,Lead Free(Y/N): +/-5%; Datasheet: \\172.29.17.1\cn\WLAN\WLAN2\boarddesignLIB\194_component_database\Datasheet\Resistor\Resistor_Walsin_chipR.pdf
U1 = PL2303GC_QFN: USB to RS232,RS422,RS485, 16 GPIO pins can be used; Part Number: PL2303G4FIG7P2; Part Type: USB IC; Datasheet: \\172.29.17.1\cn\WLAN\WLAN2\boarddesignLIB\01_component_database\Datasheet\Communicaton Interface Chip\USB2UART_Prolific_PL2303GC
U2 = SY8121C1ABC: 2A Load Current, 1.2MHz Switching Freq; Part Type: DCDC; Datasheet: \\172.29.17.1\cn\WLAN\WLAN2\boarddesignLIB\01_component_database\Datasheet\Power Supply ChipDCDC_Silergy, AN_SY8121C1.pdf
U3 = RT9048GSP: 2A,1.4V to 6V.; Datasheet: \\172.29.17.1\cn\WLAN\WLAN2\boarddesignLIB\01_component_database\Datasheet\Power Supply Chip\LDO_RICHTEK_RT9048GSP.pdf
U4 = UMH3N: 2个NPN-预偏置 100mA 50V; Part Type: NPN-BJT; Datasheet: \\172.29.17.1\cn\WLAN\WLAN2\boarddesignLIB\01_component_database\Datasheet\Triode-MOS Tube-Transistor\NPN-BJT_ROHM, UMH3NTN.pdf

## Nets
AVDD: C40.1 R109.2 U10.18(AVDD)
GND: C1.2 C2.2 C3.2 C4.2 C5.2 C6.2 C7.2 C9.2 C10.2 C12.2 C13.2 C14.2 C15.2 C16.2 C17.2 C18.2 C19.2 C20.2 C21.2 C22.1 C23.2 C24.2 C25.2 C26.2 C27.2 C28.2 C29.2 C30.2 C31.2 C33.2 C34.2 C35.2 C36.2 C37.2 C38.2 C39.2 C40.2 C42.2 C43.2 C44.2 C45.1 C46.2 C47.2 C48.2 C49.2 C50.2 C51.2 CN1.1(GND) CN1.10(GND) CN1.24(GND) CN1.26(GND) CN1.29(GND) CN1.41(GND) CN1.52(GND) CN1.54(GND) CN2.1(GND) CN2.10(GND) CN2.20(GND) CN2.22(GND) CN2.25(GND) CN2.33(GND) CN2.44(GND) CN2.46(GND) CON1.1(GND) CON1.7(GND) CON1.8(GND) CON1.13(GND) CON1.16(GND) CON1.17(GND) CON1.20(GND) CON1.31(GND) CON1.32(GND) CON1.33(GND) CON2.4 CON2.7(GND) CON2.8(GND) D1.2 D2.2 D3.2 D4.2 D5.2 D6.2 D9.2(CATHODE) D10.2 D11.2 D12.2 D13.2 D14.2 D15.2 D16.2 D17.2 J1.1(GND) J1.8(GND) J1.9(GND) J1.16(GND) J2.1(GND) J2.8(GND) J2.9(GND) J2.16(GND) J10.2 J10.3 J10.6 J10.7 J10.10 J10.11 J10.14 J11.6 J11.9 J11.14 J11.20 J11.25 J11.30 J11.34 J11.39 J14.4 J14.5 J15.1 J15.2 J15.4 J15.5 J18.3(GND1) J18.4(GND2) Q1.2(SOURCE) R3.2 R4.2 R5.2 R6.2 R7.2 R8.2 R14.2 R15.2 R17.2 R21.2 R91.1 R103.1 R113.1 R125.2 TP1.1 TP2.1 TP3.1 TP4.1 U1.25(GND) U2.2(GND) U3.8(GND) U3.9(EPAD) U5.1 U5.7(GND) U5.8(GND) U8.5(GND) U8.6(GND) U8.7(GND) U8.8(GND) U9.2(L/R) U9.5(GND) U9.6(GND) U9.7(GND) U9.8(GND) U10.10(DGND) U10.13(PGND) U10.14(PGND) U10.19(AGND) U10.21(EPAD)
PVDD: C42.1 C43.1 C50.1 C51.1 R108.2 U10.12(PVDD)
VCC_SDIO: C30.1 C31.1 J10.1 R88.2
VCCIO: C7.1 R9.2 R10.1 R11.1 R18.2 U1.24(VDD_IO)
ADR: R116.2 U10.5(ADR)
BAT_MEAS: CN1.2(BAT_MEAS) CN2.2(BAT_MEAS) R123.1
BYPASS: C44.1 U10.17(BYPASS)
CC1: J1.3(CC1) R3.1
CC2: J1.11(CC2) R5.1
CC_1: J2.3(CC1) R4.1
CC_2: J2.11(CC2) R6.1
CHIP_EN: C33.1 CN1.23(CHIP_EN) CN2.19(CHIP_EN) D10.1 J15.3 R27.1 R90.1 TP5.1
DISPLAY_VDD: CON1.4(LEDA) CON1.5(LEDA) CON1.6(LCD_3.3V) CON1.30(TOUCH_VDD) CON2.5 R124.2
DTR_N: R26.2 U1.22(DTR_N) U4.1(E0)
I2S_BCLK: R119.1 U10.7(SCLK)
I2S_DOUT: R120.1 U10.8(SDIN)
I2S_MCLK: R118.1 R133.1 U10.6(MCLK)
I2S_WS: R121.1 U10.9(LRCK)
PA8: CN1.27(PA8) J11.38
PA12: CN1.28(PA12) CN2.24(PA12) J11.7 R133.2
PA13: CN1.30(PA13) J13.1
PA14: CN1.31(PA14) J13.2
PA15: CN1.32(PA15) J13.3
PA16: CN1.33(PA16) J12.1
PA17: CN1.34(PA17) J12.2
PA18: CN1.35(PA18) J12.3
PA19: CN1.36(PA19) R28.1 R29.1
PA19_OSPI_CLK: CON1.18(CLK) R29.2
PA20/PA16: CN1.37(PA20) CN2.29(PA16) R30.1 R31.1
PA20_OSPI_CSN: CON1.19(CS) R31.2
PA21/PA17: CN1.38(PA21) CN2.30(PA17) R32.1 R33.1
PA21_OSPI_DC_SEL: CON1.25(DCX) R33.2
PA22: CN1.39(PA22) CN2.31(PA18) J11.26 J17.4 R120.2
PA23: CN1.40(PA23) CN2.32(PA15) J11.19 J17.5 R119.2
PA26: CN1.42(PA26) J16.1 R94.1 R111.2 R132.1 U10.3(SCL)
PA27: CN1.43(PA27) J16.2 R96.1 R115.2 R131.1 U10.2(SDA)
PA28: CN1.44(PA28) CN2.36(PA28) R34.1 R35.1
PA28_FSDM: D4.1 J2.5(DN1) J2.13(DN2) R35.2
PA29: CN1.45(PA29) CN2.37(PA29) R36.1 R37.1
PA29_FSDP: D5.1 J2.4(DP1) J2.12(DP2) R37.2
PA_19: J17.1 R28.2 R118.2
PA_20: J11.21 J17.2 R30.2 R121.2
PA_21: J11.24 J17.3 R32.2
PA_28: J11.11 R34.2
PA_29: J11.29 R36.2
PA_30: CN1.46(PA30) CN2.38(PA14) J11.23
PA_31: CN1.47(PA31) J19.1 R110.1 R113.2 U10.1(\\~{S}D)
PB0/PA30: CN1.48(PB0) CN2.40(PA30) R40.1 R41.1 R42.1
PB0_DMIC_CLK: D14.1 D16.1 R42.2 U8.3(CLK) U9.3(CLK)
PB0_TE: CON1.15(TE) R41.2
PB1/PA31: CN1.49(PB1) CN2.41(PA31) R43.1 R44.1 R45.1 R128.1
PB1_DMIC_DATA: D15.1 D17.1 R45.2 U8.4(DATA) U9.4(DATA)
PB1_TOUCH_SDA: CON2.2 R128.2
PB1_TP_SDA: CON1.26(TOUCH_SDA) R44.2
PB2/PA13: CN1.50(PB2) CN2.42(PA13) R46.1 R47.1 R129.1
PB2_TOUCH_SCL: CON2.1 R129.2
PB2_TP_SCL: CON1.27(TOUCH_SCL) R47.2
PB3/PA27: CN1.51(PB3) CN2.43(PA27) R48.1 R49.1 R130.1
PB3_TOUCH_INT: CON2.3 R130.2
PB3_TP_INT: CON1.29(TOUCH_INT) R49.2
PB4_UART_LOG_RXD: CN1.3(PB4) CN2.3(PB4) J5.2 R20.2
PB5_UART_LOG_TXD: CN1.4(PB5) CN2.4(PB5) D11.1 J6.2 J14.3 R22.2 R89.1
PB6/PA26: CN1.5(PB6) CN2.5(PA26) R50.1 R51.1 R52.1
PB6_OSPI_D0: CON1.12(D0) R52.2
PB6_SDIO_D2: J11.37 R50.2
PB7/PB17: CN1.6(PB7) CN2.6(PB17) R53.1 R54.1 R55.1
PB7_OSPI_D1: CON1.11(D1) R55.2
PB7_SDIO_D3: J11.13 R53.2
PB8/PB18: CN1.7(PB8) CN2.7(PB18) R56.1 R57.1 R58.1
PB8_OSPI_D2: CON1.10(D2) R58.2
PB8_SDIO_CMD: J11.16 R56.2
PB9/PB19: CN1.8(PB9) CN2.8(PB19) R59.1 R60.1 R61.1
PB9_OSPI_D3: CON1.9(D3) R61.2
PB9_SDIO_CLK: J11.15 R59.2
PB10: CN1.9(PB10) R62.1 R63.1
PB10_RESET: CON1.14(LCD_RESET) R63.2
PB13/PB20: CN1.11(PB13) CN2.11(PB20) R64.1 R65.1 R66.1
PB13_OSPI_D4: CON1.21(D4) R66.2
PB13_SDIO_D0: J11.18 R64.2
PB14/PB21: CN1.12(PB14) CN2.12(PB21) R67.1 R68.1 R69.1
PB14_OSPI_D5: CON1.22(D5) R69.2
PB14_SDIO_D1: J11.22 R67.2
PB15/PA8: CN1.13(PB15) CN2.13(PA8) R70.1 R72.1
PB15_OSPI_D6: CON1.23(D6) R72.2
PB16: CN1.14(PB16) R73.1 R74.1 R75.1
PB16_OSPI_D7: CON1.24(D7) R75.2
PB16_TOUCH3: R74.2 U5.2
PB17: CN1.15(PB17) R77.1 R78.1
PB17_TOUCH2: R78.2 U5.3
PB18: CN1.16(PB18) R79.1 R80.1
PB18_TOUCH1: R80.2 U5.4
PB19: CN1.17(PB19) R81.1 R82.1
PB19_TOUCH0: R82.2 U5.5
PB20: C35.1 CN1.18(PB20) J11.35
PB21: CN1.19(PB21) R83.1 R84.1
PB21_BL: R84.2 R126.1
PB22: CN1.20(PB22) R85.1 R86.1 R127.1
PB22_RST: CON1.28(TOUCH_RST) R86.2
PB22_TOUCH_RST: CON2.6 R127.2
PB30: CN1.21(PB30) CN2.17(PB30) J11.3 R97.2 R102.2
PB31: CN1.22(PB31) CN2.18(PB31) J11.5 R100.1 R103.2 R104.2
PB_0: J11.27 R40.2 R99.2
PB_1: J11.28 R43.2 R101.2
PB_2: J11.8 R46.2 R131.2
PB_3: J11.10 R48.2 R132.2
PB_10: J20.1 R62.2
PB_15: J11.12 R70.2
PB_16: J20.2 R73.2
PB_17: J19.2 R77.2
PB_18: J11.31 R79.2
PB_19: J11.33 R81.2
PB_21: C34.1 J11.32 R83.2
PB_22: J11.36 R85.2
PL2303_DN: D1.1 J1.5(DN1) J1.13(DN2) U1.11(DM)
PL2303_DP: D3.1 J1.4(DP1) J1.12(DP2) U1.10(DP)
RTS_N: R25.1 U1.23(RTS_N) U4.4(E1)
SDIO_CLK: C29.1 J10.12 R60.2
SDIO_CMD: C24.1 J10.5 R57.2
SDIO_D0: C28.1 J10.8 R65.2
SDIO_D1: C27.1 J10.4 R68.2
SDIO_D2: C26.1 J10.13 R51.2
SDIO_D3: C25.1 J10.9 R54.2
UART_LOG_RX: J5.1 R20.1 U1.21(TXD)
UART_LOG_TX: J6.1 R22.1 R24.2 U1.1(RXD)
USB0_5V: C1.1 C2.1 D2.1 J1.2(VBUS) J1.7(VBUS) J1.10(VBUS) J1.15(VBUS) R1.1
USB1_5V: C3.1 C4.1 D6.1 J2.2(VBUS) J2.7(VBUS) J2.10(VBUS) J2.15(VBUS) R2.1
VD5V: C9.1 C10.1 C14.1 C18.1 C19.1 J3.1 J11.2 J11.4 R1.2 R2.2 R12.1 R108.1 R123.2 U1.14(VIN) U2.5(VIN) U3.2(EN) U3.3(VIN)
VD33: J11.1 J11.17 R87.2
VD33_APA: C46.1 C47.1 C48.1 R109.1 R111.1 R112.2 R115.1 R116.1 U10.4(DVDD)
VD1833: J7.1 R9.1 R23.1 R76.1 R87.1 R88.1 R89.2 R90.2 R99.1 R100.2 R101.1 R102.1 R104.1 R106.1 R107.1 R112.1 R122.2 R124.1 U7.2(VDD)
VD1833_0: C11.1 C12.1 C13.1 C20.1 C21.1 J4.1 L1.2 R13.1 R19.1 R122.1 U3.6(VOUT)
VD1833_M: C23.1 CN1.25(VDD33) CN2.21(VDD33) J7.2 R76.2
N03054: C5.1 J1.17(PAD) J1.18(PAD) J1.19(PAD) J1.20(PAD) R7.1
N03142: C6.1 J2.17(PAD) J2.18(PAD) J2.19(PAD) J2.20(PAD) R8.1
N03668: C22.2 R27.2 U4.3(C1)
N03736: R24.1 U4.6(C0)
N03798: R26.1 U4.5(B1)
N03802: R25.2 U4.2(B0)
N03858: D9.1(ANODE) R23.2
N04456: D8.2(CATHODE) U1.16(GPB1)
N04460: D8.1(ANODE) R10.2
N04490: D7.1(ANODE) R11.2
N04526: D7.2(CATHODE) U1.15(GPB0)
N04622: C15.1 R18.1 U1.13(RESET_N)
N04726: C16.1 C17.1 U1.12(VO_33)
N05616: C11.2 R13.2 R14.1 R16.1 U2.3(FB)
N05902: R19.2 R21.1 U3.7(ADJ)
N06090: C8.2 L1.1 U2.6(LX)
N06094: C8.1 U2.1(BS)
N06238: R12.2 R15.1 U2.4(EN)
N06424: R16.2 R17.1
N21368: R110.2 U10.20(FAULT)
N21390: C38.1 C39.1 D13.1 R107.2 U9.1(VDD)
N21510: C36.1 C37.1 D12.1 R106.2 U8.1(VDD) U8.2(L/R)
N23094: C45.2 J18.1(S1) L2.2
N23100: C49.1 J18.2(S2) L3.2
N16793416: J14.1 J14.2 R91.2
N16802801: R97.1 U7.4(Blue)
N16802803: R94.2 U7.1(Red)
N16802805: R96.2 U7.3(Green)
N16874589: L2.1 U10.15(OUTN)
N16874623: L3.1 U10.11(OUTP)
N16986193: CON1.2(LEDK) CON1.3(LEDK) Q1.3(DRAIN)
N17017935: Q1.1(GATE) R125.1 R126.2

Not connected (* = marked no-connect by the designer): CN1 53(NC)*; CN2 9(NC)* 14(NC)* 15(NC)* 16(NC)* 23(NC)* 26(NC)* 27(NC)* 28(NC)* 34(NC)* 35(NC)* 39(NC)* 45(NC)*; H1 1*; H2 1*; H3 1*; H4 1*; J1 6(SBU1) 14(SBU2)*; J2 6(SBU1) 14(SBU2)*; J11 40*; U1 2(RI_N)* 3(TXEN)* 4(DSR_N)* 5(DCD_N)* 6(CTS_N)* 7(SUSP_N)* 8(GPB3)* 9(GPB2)* 17(GPB4)* 18(GPB5)* 19(XI)* 20(XO)*; U3 1(NC)* 4(NC)* 5(NC)*; U5 6*; U10 16(NC)*

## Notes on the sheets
sheet 1
- Block Diagram
- Diplexer
- GPIO
  Pin Header
- USB
- Audio PA
- RL6845 module
  QFN68
- DMIC*2
- OSPI
- SDIO
- XTAL
- DCDC/LDO
- USB2UART
sheet 2
- Power Tree
- USB TypeC
- 5V
- USB to UART
- System Power Option 3.3V
- System Power Option 1.8V
- 1.8V
- 1.8V_WL
- 5V
- USB Host
- DCDC or LDO
  5V to 3.3/1.8V
- LDOM
  (OFF)
- 3.3V
- 3.3V_WL
- 1.8V
- LDOM
  (1.8V)
  (ON/OFF)
- 1.8V
- Battery Supply
  from Jumper
- DCDC
  (1.25V)
- 1.25V
- DCDC
  (1.25V)
- 1.25V
- SDIO Host
- LDOC
  (0.9V)
- 0.9V
- LDOC
  (0.9V)
- 0.9V
- for 0.9V pins
- for 0.9V pins
- for 1.25V pins
- for 1.25V pins
- for 1.8V pins
- for 1.8V pins
- for 3.3V pins
- other blocks
- other blocks
sheet 3
- USB TO UART
- USB Type-C
- USB Type-C
- PL2303_DP/DN 90oHm impedance
- USB_DP/DN 90oHm impedance
- PL2303GC QFN24 4X4
- +5V to +3.3V or +1.8V DCDC
- Vout=0.6*[1+100/(49.9//39)]=3.34V
  Vout=0.6*(1+100/49.9)=1.8V
- Remove 39K for 1.8V output
- +5V to +3.3V LDO
- Reserved for Battery Supply
- Vout=0.5*(1+100/18)=3.28V
- Power indicator
- Auto download
- For cases where auto download is not
  required，this circuit can be NC
sheet 4
- QFN48
- QFN68
- for QFN68 MODULE
- for QFN48 MODULE
- Because the QFN68 and QFN48 modules share the same
  motherboard, the GPIOs have been stacked. When pasting
  the QFN68 module, the output pins connect left GPIOs,
  while when pasting the QFN48 module, the output pins
  connect rignt GPIOs.
sheet 5
- CAP TOUCH IF
- 40 PIN Header
- Pin Header for SDIO Golden Finger
- I2C1_SDA
- I2C1_SCL
- UART1_RXD
- UART1_TXD
- Placed near main IC
  Reserved for filtering digital
  interference to WiFi
- SPI0_MISO
- SPI0_MOSI
- SPI0_CLK
- SPI0_CS
- Powered by SDIO Host
- Others
- I2C0_SDA
- I2C0_SCL
- Download Button
- Chip_EN Button
- OSPI
- User LED
- Reserve for internal test
- I2C pull-up
- SIC
- test mode select
sheet 6
- DMIC
- L/R=HIGH，CLK=HIGH,DATA=VALID      L/R=LOW，CLK=LOW,DATA=VALID
- Reserved RC Filter
- Reserved RC Filter
- Audio Amplifier
- I2S_MCLK
- I2S_WS
- I2S_DIN
- I2S_DOUT
- I2S_BCLK
- Audio PA can only works under 3.3v.
